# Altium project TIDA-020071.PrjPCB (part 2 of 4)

## Sheet 818-03.SchDoc
size A3; Date: Not shown in title block; ApprovedBy: Not shown in title block; CheckedBy: Not shown in title block; Author: Not shown in title block; CompanyName: Not shown in title block; Engineer: Not shown in title block; Organization: Not shown in title block; Address1: Not shown in title block; Address2: Not shown in title block; Address3: Not shown in title block; Address4: Not shown in title block; DocumentNumber: 4; Revision: Use project parameter SCH_Rev; SheetNumber: 4; SheetTotal: 15; PageSetup: Record=PageOptions¦CenterHorizontal=True¦CenterVertical=True¦PrintScale=1.00¦XCorrection=1.00¦YCorrection=1.00¦PrintKind=0¦BorderSize=5000000¦LeftOffset=0¦BottomOffset=0¦Orientation=2¦PaperLength=1000¦PaperWidth=1000¦Scale=100¦PaperSource=15¦PrintQuality=600¦MediaType=1¦DitherType=10¦PaperKind=Letter¦PrintScaleMode=1
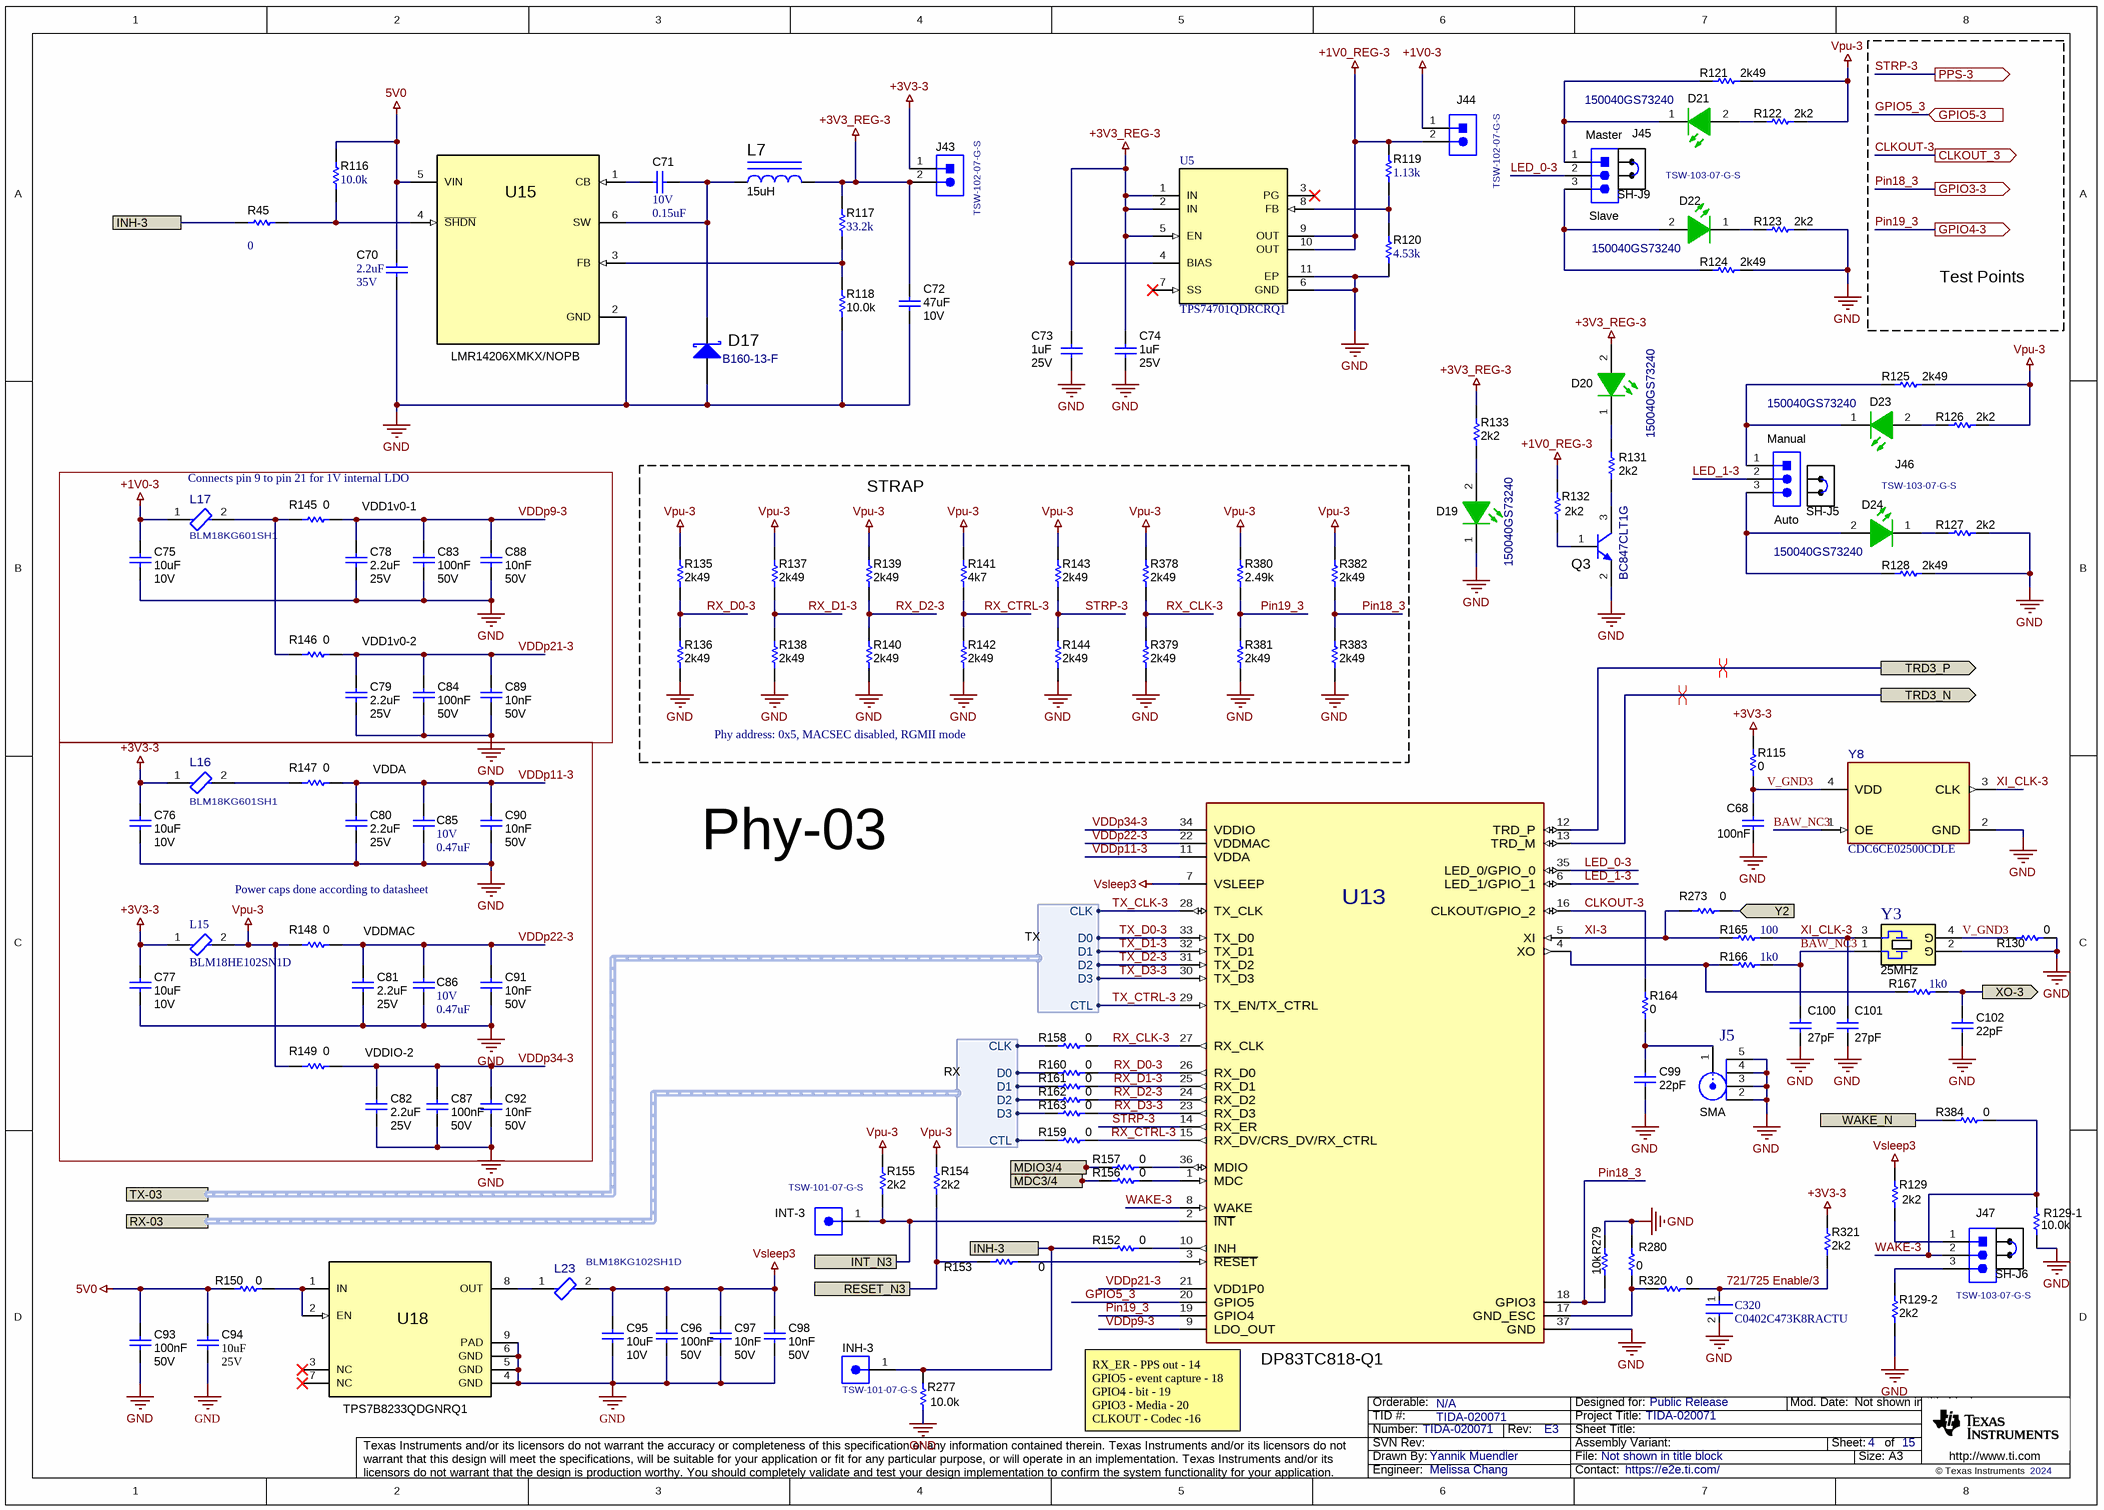
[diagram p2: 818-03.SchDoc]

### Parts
C68  ValueDisplayed: 100nF  [0402]  (hidden comment: C1005X5R1H104K050BB)
C70  VDC_V: 35V  ValueDisplayed: 2.2uF  [0603]  (hidden comment: C1608X5R1V225K080AC)
C71  VDC_V: 10V  ValueDisplayed: 0.15uF  [0402]  (hidden comment: GRM155R61A154KE19D)
C72  VDC_V: 10V  ValueDisplayed: 47uF  [0805_HV]  (hidden comment: C2012X5R1A476M125AC)
C73  VDC_V: 25V  ValueDisplayed: 1uF  [0402]  (hidden comment: GRM155R61E105KA12D)
C74  VDC_V: 25V  ValueDisplayed: 1uF  [0402]  (hidden comment: GRM155R61E105KA12D)
C75  VDC_V: 10V  ValueDisplayed: 10uF  [0402]  (hidden comment: GRM155R61A106ME11)
C76  VDC_V: 10V  ValueDisplayed: 10uF  [0402]  (hidden comment: GRM155R61A106ME11)
C77  VDC_V: 10V  ValueDisplayed: 10uF  [0402]  (hidden comment: GRM155R61A106ME11)
C78  VDC_V: 25V  ValueDisplayed: 2.2uF  [0402]  (hidden comment: C1005X5R1E225K050BC)
C79  VDC_V: 25V  ValueDisplayed: 2.2uF  [0402]  (hidden comment: C1005X5R1E225K050BC)
C80  VDC_V: 25V  ValueDisplayed: 2.2uF  [0402]  (hidden comment: C1005X5R1E225K050BC)
C81  VDC_V: 25V  ValueDisplayed: 2.2uF  [0402]  (hidden comment: C1005X5R1E225K050BC)
C82  VDC_V: 25V  ValueDisplayed: 2.2uF  [0402]  (hidden comment: C1005X5R1E225K050BC)
C83  VDC_V: 50V  ValueDisplayed: 100nF  [0402]  (hidden comment: C1005X5R1H104K050BB)
C84  VDC_V: 50V  ValueDisplayed: 100nF  [0402]  (hidden comment: C1005X5R1H104K050BB)
C85  VDC_V: 10V  ValueDisplayed: 0.47uF  [0402]  (hidden comment: GRM155R61A474KE15D)
C86  VDC_V: 10V  ValueDisplayed: 0.47uF  [0402]  (hidden comment: GRM155R61A474KE15D)
C87  VDC_V: 50V  ValueDisplayed: 100nF  [0402]  (hidden comment: C1005X5R1H104K050BB)
C88  VDC_V: 50V  ValueDisplayed: 10nF  [0402]  (hidden comment: C0402C103J5RACTU)
C89  VDC_V: 50V  ValueDisplayed: 10nF  [0402]  (hidden comment: C0402C103J5RACTU)
C90  VDC_V: 50V  ValueDisplayed: 10nF  [0402]  (hidden comment: C0402C103J5RACTU)
C91  VDC_V: 50V  ValueDisplayed: 10nF  [0402]  (hidden comment: C0402C103J5RACTU)
C92  VDC_V: 50V  ValueDisplayed: 10nF  [0402]  (hidden comment: C0402C103J5RACTU)
C93  VDC_V: 50V  ValueDisplayed: 100nF  [0402]  (hidden comment: C1005X5R1H104K050BB)
C94  VDC_V: 25V  ValueDisplayed: 10uF  [0603]  (hidden comment: C1608X5R1E106M080AC)
C95  VDC_V: 10V  ValueDisplayed: 10uF  [0402]  (hidden comment: GRM155R61A106ME11)
C96  VDC_V: 50V  ValueDisplayed: 100nF  [0402]  (hidden comment: C1005X5R1H104K050BB)
C97  VDC_V: 50V  ValueDisplayed: 10nF  [0402]  (hidden comment: C0402C103J5RACTU)
C98  VDC_V: 50V  ValueDisplayed: 10nF  [0402]  (hidden comment: C0402C103J5RACTU)
C99  ValueDisplayed: 22pF  [0402]  (hidden comment: GRM1555C1H220FA01D)
C100  ValueDisplayed: 27pF  [0402]  (hidden comment: C0402C270J5GACTU)
C101  ValueDisplayed: 27pF  [0402]  (hidden comment: C0402C270J5GACTU)
C102  ValueDisplayed: 22pF  [0402]  (hidden comment: GRM1555C1H220FA01D)
C320  C0402C473K8RACTU  [FP-C0402-BB-MFG]
D17  B160-13-F  [SMA]
D19  150040GS73240  [WL-SMCC_0402_Green]
D20  150040GS73240  [WL-SMCC_0402_Green]
D21  150040GS73240  [WL-SMCC_0402_Green]
D22  150040GS73240  [WL-SMCC_0402_Green]
D23  150040GS73240  [WL-SMCC_0402_Green]
D24  150040GS73240  [WL-SMCC_0402_Green]
INH-3  TSW-101-07-G-S  [TSW-101-07-G-S]
INT-3  TSW-101-07-G-S  [TSW-101-07-G-S]
J5  CompType: SMA  [AMPHENOL_901-144-8RFX]  (hidden comment: 901-144-8RFX)
J43  TSW-102-07-G-S  [TSW-102-07-G-S]
J44  TSW-102-07-G-S  [TSW-102-07-G-S]
J45  TSW-103-07-G-S  [TSW-103-07-G-S]
J46  TSW-103-07-G-S  [TSW-103-07-G-S]
J47  TSW-103-07-G-S  [TSW-103-07-G-S]
L7  ValueDisplayed: 15uH  [WE-TPC-LH]  (hidden comment: 744053150)
L15  BLM18HE102SN1D  [FP-BLM18-0_15-t0_8-MFG]
L16  BLM18KG601SH1  [FP-BLM18KG601SH1_0603 (1608 Metric)-MFG]
L17  BLM18KG601SH1  [FP-BLM18KG601SH1_0603 (1608 Metric)-MFG]
L23  BLM18KG102SH1D  [FP-BLM18KG102SH1D_0603-MFG]
Q3  BC847CLT1G  [SOT-23]
R45  ValueDisplayed: 0  [0402]  (hidden comment: CRCW04020000Z0ED)
R115  ValueDisplayed: 0  [0402]  (hidden comment: ERJ-2GE0R00X)
R116  ValueDisplayed: 10.0k  [0402]  (hidden comment: CRCW040210K0FKED)
R117  ValueDisplayed: 33.2k  [0402]  (hidden comment: CRCW040233K2FKED)
R118  ValueDisplayed: 10.0k  [0402]  (hidden comment: CRCW040210K0FKED)
R119  ValueDisplayed: 1.13k  [0402]  (hidden comment: CRCW04021K13FKED)
R120  ValueDisplayed: 4.53k  [0402]  (hidden comment: CRCW04024K53FKED)
R121  ValueDisplayed: 2k49  [0402]  (hidden comment: CRCW04022K49FKED)
R122  ValueDisplayed: 2k2  [0402]  (hidden comment: CRCW04022K20JNED)
R123  ValueDisplayed: 2k2  [0402]  (hidden comment: CRCW04022K20JNED)
R124  ValueDisplayed: 2k49  [0402]  (hidden comment: CRCW04022K49FKED)
R125  ValueDisplayed: 2k49  [0402]  (hidden comment: CRCW04022K49FKED)
R126  ValueDisplayed: 2k2  [0402]  (hidden comment: CRCW04022K20JNED)
R127  ValueDisplayed: 2k2  [0402]  (hidden comment: CRCW04022K20JNED)
R128  ValueDisplayed: 2k49  [0402]  (hidden comment: CRCW04022K49FKED)
R129  ValueDisplayed: 2k2  [0402]  (hidden comment: CRCW04022K20JNED)
R129-1  ValueDisplayed: 10.0k  [0402]  (hidden comment: CRCW040210K0FKED)
R129-2  ValueDisplayed: 2k2  [0402]  (hidden comment: CRCW04022K20JNED)
R130  ValueDisplayed: 0  [0402]  (hidden comment: ERJ-2GE0R00X)
R131  ValueDisplayed: 2k2  [0402]  (hidden comment: CRCW04022K20JNED)
R132  ValueDisplayed: 2k2  [0402]  (hidden comment: CRCW04022K20JNED)
R133  ValueDisplayed: 2k2  [0402]  (hidden comment: CRCW04022K20JNED)
R135  ValueDisplayed: 2k49  [0402]  (hidden comment: CRCW04022K49FKED)
R136  ValueDisplayed: 2k49  [0402]  (hidden comment: CRCW04022K49FKED)
R137  ValueDisplayed: 2k49  [0402]  (hidden comment: CRCW04022K49FKED)
R138  ValueDisplayed: 2k49  [0402]  (hidden comment: CRCW04022K49FKED)
R139  ValueDisplayed: 2k49  [0402]  (hidden comment: CRCW04022K49FKED)
R140  ValueDisplayed: 2k49  [0402]  (hidden comment: CRCW04022K49FKED)
R141  ValueDisplayed: 4k7  [0402]  (hidden comment: RC0402FR-074K7L)
R142  ValueDisplayed: 2k49  [0402]  (hidden comment: CRCW04022K49FKED)
R143  ValueDisplayed: 2k49  [0402]  (hidden comment: CRCW04022K49FKED)
R144  ValueDisplayed: 2k49  [0402]  (hidden comment: CRCW04022K49FKED)
R145  ValueDisplayed: 0  [0402]  (hidden comment: CRCW04020000Z0EDHP)
R146  ValueDisplayed: 0  [0402]  (hidden comment: CRCW04020000Z0EDHP)
R147  ValueDisplayed: 0  [0402]  (hidden comment: CRCW04020000Z0EDHP)
R148  ValueDisplayed: 0  [0402]  (hidden comment: CRCW04020000Z0EDHP)
R149  ValueDisplayed: 0  [0402]  (hidden comment: CRCW04020000Z0EDHP)
R150  ValueDisplayed: 0  [0402]  (hidden comment: CRCW04020000Z0EDHP)
R152  ValueDisplayed: 0  [0402]  (hidden comment: CRCW04020000Z0EDHP)
R153  ValueDisplayed: 0  [0402]  (hidden comment: CRCW04020000Z0EDHP)
R154  ValueDisplayed: 2k2  [0402]  (hidden comment: CRCW04022K20JNED)
R155  ValueDisplayed: 2k2  [0402]  (hidden comment: CRCW04022K20JNED)
R156  ValueDisplayed: 0  [0402]  (hidden comment: CRCW04020000Z0EDHP)
R157  ValueDisplayed: 0  [0402]  (hidden comment: CRCW04020000Z0EDHP)
R158  ValueDisplayed: 0  [0402]  (hidden comment: CRCW04020000Z0EDHP)
R159  ValueDisplayed: 0  [0402]  (hidden comment: CRCW04020000Z0EDHP)
R160  ValueDisplayed: 0  [0402]  (hidden comment: CRCW04020000Z0EDHP)
R161  ValueDisplayed: 0  [0402]  (hidden comment: CRCW04020000Z0EDHP)
R162  ValueDisplayed: 0  [0402]  (hidden comment: CRCW04020000Z0EDHP)
R163  ValueDisplayed: 0  [0402]  (hidden comment: CRCW04020000Z0EDHP)
R164  ValueDisplayed: 0  [0402]  (hidden comment: ERJ-2GE0R00X)
R165  ValueDisplayed: 100  [0402]  (hidden comment: CRCW0402100RFKED)
R166  ValueDisplayed: 1k0  [0402]  (hidden comment: CRCW04021K00FKED)
R167  ValueDisplayed: 1k0  [0402]  (hidden comment: CRCW04021K00FKED)
R273  ValueDisplayed: 0  [0402]  (hidden comment: ERJ-2GE0R00X)
R277  ValueDisplayed: 10.0k  [0402]  (hidden comment: CRCW040210K0FKED)
R279  ValueDisplayed: 10k  [0402]  (hidden comment: ERJ-2RKF1002X)
R280  ValueDisplayed: 0  [0402]  (hidden comment: ERJ-2GE0R00X)
R320  ValueDisplayed: 0  [0402]  (hidden comment: CRCW04020000Z0EDHP)
R321  ValueDisplayed: 2k2  [0402]  (hidden comment: CRCW04022K20JNED)
R378  ValueDisplayed: 2k49  [0402]  (hidden comment: CRCW04022K49FKED)
R379  ValueDisplayed: 2k49  [0402]  (hidden comment: CRCW04022K49FKED)
R380  ValueDisplayed: 2.49k  [0402]  (hidden comment: CRCW04022K49FKED)
R381  ValueDisplayed: 2k49  [0402]  (hidden comment: CRCW04022K49FKED)
R382  ValueDisplayed: 2k49  [0402]  (hidden comment: CRCW04022K49FKED)
R383  ValueDisplayed: 2k49  [0402]  (hidden comment: CRCW04022K49FKED)
R384  ValueDisplayed: 0  [0402]  (hidden comment: CRCW04020000Z0EDHP)
SH-J5  881545-2  [TE_881545-2]  (value not drawn)  (mechanical)
SH-J6  881545-2  [TE_881545-2]  (value not drawn)  (mechanical)
SH-J9  881545-2  [TE_881545-2]  (value not drawn)  (mechanical)
U5  TPS74701QDRCRQ1  [DRC0010A]
U13  PartNumber: DP83TC818-Q1  [RHA0036A-MFG]  (hidden comment: DP83TC812R-Q1)
U15  LMR14206XMKX/NOPB  [DDC0006A_N]
U18  TPS7B8233QDGNRQ1  [DGN0008D_N]
Y3  Frequency_Fixed: 25MHz  [Abracon_ABM8AIG]  (hidden comment: ABM8AIG-25.000MHZ-12-2Z-T3)
Y8  CDC6CE02500CDLE  [DLE0004A-MFG]

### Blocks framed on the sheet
STRAP: R135-R144 R378-R383

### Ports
CLKOUT_3 (out), GPIO3-3 (out), GPIO4-3 (out), GPIO5-3 (in), INH-3, INT_N3, MDC3/4, MDIO3/4, PPS-3 (out), RESET_N3, RX-03 (harness RX), TRD3_N (out), TRD3_P (out), TX-03 (harness TX), WAKE_N, XO-3 (out), Y2 (in)

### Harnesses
TX: D0, D1, D2, D3, CTL, CLK
RX: D0, D1, D2, D3, CTL, CLK

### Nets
5V0: C70.1 C93.1 C94.1 R116.2 R150.2 U15.5(VIN)
+1V0-3: C75.1 J44.1 L17.1
+1V0_REG-3: J44.2 R119.2 R132.2 U5.9(OUT) U5.10(OUT)
+3V3-3: C76.1 C77.1 J43.1 L15.1 L16.1 R115.1 R321.1
+3V3_REG-3: C72.1 C73.1 C74.1 D20.2(A) J43.2 L7.2 R117.2 R133.2 U5.1(IN) U5.2(IN) U5.4(BIAS) U5.5(EN)
GND: C68.2 C70.2 C72.2 C73.2 C74.2 C75.2 C76.2 C77.2 C78.2 C79.2 C80.2 C81.2 C82.2 C83.2 C84.2 C85.2 C86.2 C87.2 C88.2 C89.2 C90.2 C91.2 C92.2 C93.2 C94.2 C95.2 C96.2 C97.2 C98.2 C99.2 C100.2 C101.2 C102.2 C320.2 D17.2(A) D19.1(K) J5.2 J5.3 J5.4 J5.5 Q3.2(E) R118.1 R120.1 R123.2 R124.2 R127.2 R128.2 R129-1.1 R129-2.2 R130.2 R136.1 R138.1 R140.1 R142.1 R144.1 R277.1 R279.1 R280.1 R379.1 R381.1 R383.1 U5.6(GND) U5.11(EP) U13.37(GND) U15.2(GND) U18.4(GND) U18.5(GND) U18.6(GND) U18.9(PAD) Y3.2(GND) Y8.2(GND)
Vpu-3: L15.2 R121.2 R122.2 R125.2 R126.2 R135.2 R137.2 R139.2 R141.2 R143.2 R148.2 R149.2 R154.2 R155.2 R378.2 R380.2 R382.2
Vsleep3: C95.1 C96.1 C97.1 C98.1 L23.2 R129.1 U13.7(VSLEEP)
721/725 Enable/3: C320.1 R320.1 R321.2
BAW_NC3: C100.1 R166.1 Y3.1 Y8.1(OE)
CLKOUT-3: R164.1 R166.2 R167.2 U13.4(XO) U13.16(CLKOUT/GPIO_2) ; port CLKOUT_3
GPIO5_3: U13.20(GPIO5) ; port GPIO5-3
INH-3: INH-3.1 R45.1 R152.2 R277.2 ; port INH-3
INT_N3: INT-3.1 R155.1 U13.2(~{INT}) ; port INT_N3
LED_0-3: J45.2 U13.35(LED_0/GPIO_0)
LED_1-3: J46.2 U13.6(LED_1/GPIO_1)
MDC3/4: R156.2 ; port MDC3/4
MDIO3/4: R157.2 ; port MDIO3/4
P0-R1-RCLK: R158.2 ; port RX-03.CLK
P0-R1-RCTL: R159.2 ; port RX-03.CTL
P0-R1-RD0: R160.2 ; port RX-03.D0
P0-R1-RD1: R161.2 ; port RX-03.D1
P0-R1-RD2: R162.2 ; port RX-03.D2
P0-R1-RD3: R163.2 ; port RX-03.D3
Pin18_3: R279.2 R382.1 R383.2 U13.18(GPIO3) ; port GPIO3-3
Pin19_3: R380.1 R381.2 U13.19(GPIO4) ; port GPIO4-3
RESET_N3: R153.2 R154.1 ; port RESET_N3
RX_CLK-3: R158.1 R378.1 R379.2 U13.27(RX_CLK)
RX_CTRL-3: R141.1 R142.2 R159.1 U13.15(RX_DV/CRS_DV/RX_CTRL)
RX_D0-3: R135.1 R136.2 R160.1 U13.26(RX_D0)
RX_D1-3: R137.1 R138.2 R161.1 U13.25(RX_D1)
RX_D2-3: R139.1 R140.2 R162.1 U13.24(RX_D2)
RX_D3-3: R163.1 U13.23(RX_D3)
STRP-3: R143.1 R144.2 U13.14(RX_ER) ; port PPS-3
TRD3_N: U13.13(TRD_M) ; port TRD3_N
TRD3_P: U13.12(TRD_P) ; port TRD3_P
TX_CLK-3: U13.28(TX_CLK) ; port TX-03.CLK
TX_CTRL-3: U13.29(TX_EN/TX_CTRL) ; port TX-03.CTL
TX_D0-3: U13.33(TX_D0) ; port TX-03.D0
TX_D1-3: U13.32(TX_D1) ; port TX-03.D1
TX_D2-3: U13.31(TX_D2) ; port TX-03.D2
TX_D3-3: U13.30(TX_D3) ; port TX-03.D3
V_GND3: C68.1 R115.2 R130.1 Y3.4(GND) Y8.4(VDD)
VDDp9-3: C78.1 C83.1 C88.1 R145.1 U13.9(LDO_OUT)
VDDp11-3: C80.1 C85.1 C90.1 R147.1 U13.11(VDDA)
VDDp21-3: C79.1 C84.1 C89.1 R146.1 U13.21(VDD1P0)
VDDp22-3: C81.1 C86.1 C91.1 R148.1 U13.22(VDDMAC)
VDDp34-3: C82.1 C87.1 C92.1 R149.1 U13.34(VDDIO)
WAKE-3: J47.2 R129-1.2 R384.1 U13.8(WAKE)
WAKE_N: R384.2 ; port WAKE_N
XI-3: R165.2 R273.1 U13.5(XI)
XI_CLK-3: C101.1 R165.1 Y3.3 Y8.3(CLK)
XO-3: C102.1 R167.1 ; port XO-3
Y2: R273.2 ; port Y2
NetC71_1: C71.1 D17.1(K) L7.1 U15.6(SW)
NetC71_2: C71.2 U15.1(CB)
NetC99_1: C99.1 J5.1 R164.2
NetD19_2: D19.2(A) R133.1
NetD20_1: D20.1(K) R131.2
NetD21_1: D21.1(K) J45.1 R121.1
NetD21_2: D21.2(A) R122.1
NetD22_1: D22.1(K) R123.1
NetD22_2: D22.2(A) J45.3 R124.1
NetD23_1: D23.1(K) J46.1 R125.1
NetD23_2: D23.2(A) R126.1
NetD24_1: D24.1(K) R127.1
NetD24_2: D24.2(A) J46.3 R128.1
NetJ47_1: J47.1 R129.2
NetJ47_3: J47.3 R129-2.1
NetL16_2: L16.2 R147.2
NetL17_2: L17.2 R145.2 R146.2
NetL23_1: L23.1 U18.8(OUT)
NetQ3_1: Q3.1(B) R132.1
NetQ3_3: Q3.3(C) R131.1
NetR45_2: R45.2 R116.1 U15.4(~{SHDN})
NetR117_1: R117.1 R118.2 U15.3(FB)
NetR119_1: R119.1 R120.2 U5.8(FB)
NetR150_1: R150.1 U18.1(IN) U18.2(EN)
NetR152_1: R152.1 U13.10(INH)
NetR153_1: R153.1 U13.3(~{RESET})
NetR156_1: R156.1 U13.1(MDC)
NetR157_1: R157.1 U13.36(MDIO)
NetR280_2: R280.2 R320.2 U13.17(GND_ESC)

Not connected (* = marked no-connect by the designer): U5 3(PG)* 7(SS)*; U18 3(NC)* 7(NC)*

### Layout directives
differential pair: TRD3_N, TRD3_P

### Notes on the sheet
- (near J45) Master
- (near J45) Slave
- Test Points
- (near J46) Manual
- Connects pin 9 to pin 21 for 1V internal LDO
- VDD1v0-1
- Auto
- VDD1v0-2
- VDDA
- Phy address: 0x5, MACSEC disabled, RGMII mode
- Phy-03
- Power caps done according to datasheet
- VDDMAC
- VDDIO-2
- (near U13) RX_ER - PPS out - 14
  GPIO5 - event capture - 18
  GPIO4 - bit - 19                                     GPIO3 - Media - 20
  CLKOUT - Codec -16

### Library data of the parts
C68 = CMP-0006279-2: CAP, CERM, 0.1 uF, 50 V, +/- 10%, X5R, 0402; Manufacturer: TDK; TaMin_C: -55°C; ESR_ohm: 0.039064; Polarized: N; SizeAreaWB_mm2: 3; Value1: 0.039064 ohm; U/M: EA; Value: 0.1uF; TaMax_C: 85°C; SizeZ_mm: 0.6; SizeX_mm: 1; SizeY_mm: 0.5; Value2: 50V; IRMS_A: 814.669mA; AEC Category: Q200
C70 = CMP-0007020-5: CAP, CERM, 2.2 uF, 35 V, +/- 10%, X5R, 0603; Manufacturer: TDK; TaMin_C: -55°C; ESR_ohm: 7.674m; Polarized: N; SizeAreaWB_mm2: 4.68; Value1: 0.007674 ohm; U/M: EA; Value: 2.2uF; TaMax_C: 85°C; SizeZ_mm: 1; SizeX_mm: 1.6; SizeY_mm: 0.8; SizeArea_mm2: 1.28; Cap_F: 2.2µF; IRMS_A: 1.87823A; AEC Category: Q200
C71 = CMP-0006567-2: CAP, CERM, 0.15 uF, 10 V, +/- 10%, X5R, 0402; Manufacturer: MuRata; TaMin_C: -55°C; Polarized: N; SizeAreaWB_mm2: 3; Value1: Unknown; U/M: EA; Value: 0.15uF; TaMax_C: 85°C; SizeZ_mm: 0.6; SizeX_mm: 1; SizeY_mm: 0.5; Cap_F: 150nF; AEC Category: Q200
C72 = CMP-0007825-2: CAP, CERM, 47 uF, 10 V, +/- 20%, X5R, 0805; Manufacturer: TDK; TaMin_C: -55°C; ESR_ohm: 2.94m; Polarized: N; SizeAreaWB_mm2: 6.75; Value1: 0.00294 ohm; U/M: EA; Value: 47uF; TaMax_C: 85°C; SizeZ_mm: 1.45; SizeX_mm: 2; SizeY_mm: 1.25; Cap_Case: 0805; SizeArea_mm2: 2.5; Cap_F: 47µF; IRMS_A: 3.80451A; AEC Category: Q200
C73 C74 = CMP-0006608-2: CAP, CERM, 1 uF, 25 V, +/- 10%, X5R, 0402; Manufacturer: MuRata; TaMin_C: -55°C; Polarized: N; SizeAreaWB_mm2: 3; Value1: Unknown; U/M: EA; Value: 1uF; TaMax_C: 85°C; SizeZ_mm: 0.6; SizeX_mm: 1; SizeY_mm: 0.5; Cap_F: 1µF; AEC Category: Q200
C75-C77 C95 = CMP-0006564-2: CAP, CERM, 10 uF, 10 V, +/- 20%, X5R, 0402; Manufacturer: MuRata; TaMin_C: -55°C; Polarized: N; SizeAreaWB_mm2: 3; Value1: Unknown; U/M: EA; Value: 10uF; TaMax_C: 85°C; SizeZ_mm: 0.6; SizeX_mm: 1; SizeY_mm: 0.5; Cap_F: 10µF; AEC Category: Q200
C78-C82 = CMP-0006278-2: CAP, CERM, 2.2 uF, 25 V, +/- 10%, X5R, 0402; Manufacturer: TDK; TaMin_C: -55°C; Polarized: N; SizeAreaWB_mm2: 3; Value1: Unknown; U/M: EA; Value: 2.2uF; TaMax_C: 85°C; SizeZ_mm: 0.6; SizeX_mm: 1; SizeY_mm: 0.5; Cap_F: 2.2µF; AEC Category: Q200
C83 C84 C87 C93 C96 = CMP-0006279-2: CAP, CERM, 0.1 uF, 50 V, +/- 10%, X5R, 0402; Manufacturer: TDK; TaMin_C: -55°C; ESR_ohm: 39.064m; Polarized: N; SizeAreaWB_mm2: 3; Value1: 0.039064 ohm; U/M: EA; Value: 0.1uF; TaMax_C: 85°C; SizeZ_mm: 0.6; SizeX_mm: 1; SizeY_mm: 0.5; IRMS_A: 814.669mA; AEC Category: Q200
C85 C86 = CMP-0006580-2: CAP, CERM, 0.47 uF, 10 V, +/- 10%, X5R, 0402; Manufacturer: MuRata; TaMin_C: -55°C; Polarized: N; SizeAreaWB_mm2: 3; Value1: Unknown; U/M: EA; Value: 0.47uF; TaMax_C: 85°C; SizeZ_mm: 0.6; SizeX_mm: 1; SizeY_mm: 0.5; Cap_F: 470nF; AEC Category: Q200
C88-C92 C97 C98 = CMP-0006236-2: CAP, CERM, 0.01 uF, 50 V, +/- 5%, X7R, 0402; Manufacturer: Kemet; TaMin_C: -55°C; Polarized: N; SizeAreaWB_mm2: 3; Value1: Unknown; U/M: EA; Value: 0.01uF; TaMax_C: 125°C; SizeZ_mm: 0.6; SizeX_mm: 1; SizeY_mm: 0.5; AEC Category: Q200
C94 = CMP-0007007-5: CAP, CERM, 10 uF, 25 V, +/- 20%, X5R, 0603; Manufacturer: TDK; TaMin_C: -55°C; ESR_ohm: 4.639m; Polarized: N; SizeAreaWB_mm2: 4.68; Value1: 0.004639 ohm; U/M: EA; Value: 10uF; TaMax_C: 85°C; SizeZ_mm: 1; SizeX_mm: 1.6; SizeY_mm: 0.8; SizeArea_mm2: 1.28; Cap_F: 10µF; IRMS_A: 2.41407A; AEC Category: Q200
C99 C102 = CMP-0006438-2: CAP, CERM, 22 pF, 50 V, +/- 1%, C0G/NP0, 0402; Manufacturer: MuRata; TaMin_C: -55°C; Polarized: N; SizeAreaWB_mm2: 3; Value1: Unknown; U/M: EA; Value: 22pF; TaMax_C: 125°C; SizeZ_mm: 0.6; SizeX_mm: 1; SizeY_mm: 0.5; Value2: 50V; AEC Category: Q200
C100 C101 = CMP-0750098-1: CAP, CERM, 27 pF, 50 V,+/- 5%, C0G/NP0, 0402; Manufacturer: Kemet; SizeX_mm: 1; TaMin_C: -55°C; Value: 27pF; Polarized: N; SizeAreaWB_mm2: 3; SizeArea_mm2: 0.5; Green_REACh: Passed; Green_Lifecycle: Active; Value2: 50V; U/M: EA; AEC Category: Q200; SizeZ_mm: 0.6; TaMax_C: 125°C
C320 = CMP-2008-02147-2: Cap Ceramic 0.047uF 10V X7R 10% SMD 0402 125°C Paper T/R; Manufacturer: Kemet; Temperature Coefficient: 15%; Value: 47,000 pF; Tolerance: 0.1
D17 = CMP-0028389-2: Diode, Schottky, 60 V, 1 A, SMA; Manufacturer: Diodes Inc.; Green_Lifecycle: Not Set; SizeAreaWB_mm2: 37.3428; Green_REACh: Incomplete; TJmax_C: 150°C; AEC Category: Q101; SizeZ_mm: 2.87; RJC_CperW: 20; Io_A: 1A; SizeArea_mm2: 16.3228; Vf_V: 700mV; Value2: 0.7V; SizeY_mm: 2.92; Vr_V: 60V; SizeX_mm: 5.59; Value: 60V
D19-D24 = CMP-0081765-2: LED, Green, SMD; Manufacturer: Wurth Elektronik; Vr_V: 5V; Io_A: 20mA; Tjmax_C: 95°C; Ir_A: 10µA; Power_TotalModule: 99mW; Value2: 3.2V; SizeArea_mm2: 0.5; SizeX_mm: 1; Value1: 0.099W; Angle: 120; Type: InGaN; SizeAreaWB_mm2: 3
INH-3 INT-3 = CMP-0075403-1: Header, 100mil, 1pos, Gold, TH; Manufacturer: Samtec; Pitch_mm: 2.54; Cert_VDE: N; Gender: Male; Cert_CSA: Y; Voltage_V: 550V; Green_REACh: Passed; Current_A: 6.3A; CT: False; Green_Lifecycle: Active; Row_Count: 1; CNHeader: True
J5 = CMP-0055833-1: SMA Straight Jack, Gold, 50 Ohm, TH; Manufacturer: Amphenol RF; CNHeader: FALSE; Green_Lifecycle: Not Set; Green_REACh: Incomplete; CT: TRUE
J43 J44 = CMP-0075405-3: Header, 100mil, 2x1, Gold, TH; Manufacturer: Samtec; Pitch_mm: 2.54; Cert_VDE: N; Gender: Male; Cert_CSA: Y; Voltage_V: 550V; Green_REACh: Passed; Current_A: 6.3A; Green_Lifecycle: Active; Row_Count: 1
J45-J47 = CMP-0075407-2: Header, 100mil, 3x1, Gold, TH; Manufacturer: Samtec; Pitch_mm: 2.54; Cert_VDE: N; Gender: Male; Cert_CSA: Y; Voltage_V: 550V; Green_REACh: Passed; Current_A: 6.3A; Green_Lifecycle: Active; Row_Count: 1
L7 = CMP-0064420-2: Inductor, Shielded Drum Core, Ferrite, 15 uH, 1.15 A, 0.07 ohm, SMD; Manufacturer: Wurth Elektronik; Isat: 1.15A @ 35% inductance drop; Irms: 1.38A @ 30C rise; Green_Lifecycle: Active; SizeAreaWB_mm2: 60.84; DCR_ohm: 0.07; Green_REACh: Passed; Value: 15uH; Imax_A: 1.15A; SizeZ_mm: 2.8; SizeX_mm: 5.8; SizeArea_mm2: 33.64; Ind_H: 15µH; AEC Category: Q200
L15 = CMP-0686-00363-3: Chip Ferrite Bead, 0603, 1000Ω @ 100MHz, 0.35Ω, 25%, 600mA; DC Resistance (DCR): 350mR; Impedance: 1kR; Number of Circuits: 1; Material: Steel
L16 L17 = CMP-0089848-1: 600 Ohms @ 100MHz 1 Power Line Ferrite Bead 0603 (1608 Metric) 1.3A 150mOhm; Manufacturer: Murata; Tolerance_%: 25%; SizeZ_mm: 0.95mm; Impedance At Frequency: 600Ω @ 100MHz; AEC Qualified: Yes; AEC Grade: Grade 1; DCR_ohm: 0.15
L23 = CMP-0089381-1: 1 kOhms @ 100MHz 1 Power Line Ferrite Bead 0603 (1608 Metric) 1A 200mOhm; Manufacturer: Murata; AEC Grade: Grade 1; AEC Qualified: Yes; DCR_ohm: 0.2; Impedance At Frequency: 1kΩ @ 100MHz; SizeZ_mm: 0.95mm; Tolerance_%: 25%
Q3 = CMP-0000376-2: Transistor, NPN, 45 V, 0.1 A, SOT-23; Manufacturer: ON Semiconductor; TaMax_C: 150°C; Value2: 800; Value1: 0.1 A; Vcesat1_V: 700mV; SizeX_mm: 2.5; SizeY_mm: 3; TaMin_C: -55°C; IcRated_A: 100mA; CompType: BJT; SizeZ_mm: 1.1; Value: 45 V; SizeArea_mm2: 7.5; NPN: 1; Vceo_V: 45V; PNP: 0; AEC Category: Q101; SizeAreaWB_mm2: 14; U/M: EA
R45 = CMP-0026822-1: RES, 0, 5%, 0.063 W, 0402; Manufacturer: Vishay-Dale; Power_W: 63mW; TempCo: 200 ppm/C; Value_Code: 0000; U/M: EA; Value: 0; EIA_Code: E24; SizeX_mm: 1; SizeY_mm: 0.5; SizeZ_mm: 0.6; Value2: 0.063W; VDC_V: 50V; AEC Category: Q200
R115 R130 R164 R273 R280 = CMP-0026992-3: RES, 0, 5%, 0.1 W, AEC-Q200 Grade 0, 0402; Manufacturer: Panasonic; Power_W: 100mW; TempCo: 600 ppm/C; Value_Code: 0000; Value: 0; EIA_Code: E24; SizeX_mm: 1; SizeY_mm: 0.5; SizeZ_mm: 0.6; Value2: 0.1W; AEC Qualified: Y; AEC Category: Q200; VDC_V: 50V; SizeAreaWB_mm2: 3
R116 R118 = CMP-0025958-3: RES, 10.0 k, 1%, 0.063 W, AEC-Q200 Grade 0, 0402; Manufacturer: Vishay-Dale; Power_W: 63mW; TempCo: 100 ppm/C; Value_Code: 10k0; Value: 10.0k; EIA_Code: E96; Res_ohm: 10k; SizeX_mm: 1; SizeY_mm: 0.5; SizeZ_mm: 0.6; Value2: 0.063W; AEC Qualified: Y; VDC_V: 50V; AEC Category: Q200; AEC Grade: 0
R117 = CMP-0026298-2: RES, 33.2 k, 1%, 0.063 W, AEC-Q200 Grade 0, 0402; Manufacturer: Vishay-Dale; Power_W: 63mW; TempCo: 100 ppm/C; Value_Code: 33k2; Value: 33.2k; EIA_Code: E96; SizeX_mm: 1; SizeY_mm: 0.5; SizeZ_mm: 0.6; Value2: 0.063W; AEC Qualified: Y; VDC_V: 50V; AEC Category: Q200; AEC Grade: 0
R119 = CMP-0026076-3: RES, 1.13 k, 1%, 0.063 W, AEC-Q200 Grade 0, 0402; Manufacturer: Vishay-Dale; Power_W: 63mW; TempCo: 100 ppm/C; Value_Code: 1k13; Value: 1.13k; EIA_Code: E96; SizeX_mm: 1; SizeY_mm: 0.5; SizeZ_mm: 0.6; Value2: 0.063W; AEC Qualified: Y; VDC_V: 50V; AEC Category: Q200; AEC Grade: 0
R120 = CMP-0026410-2: RES, 4.53 k, 1%, 0.063 W, AEC-Q200 Grade 0, 0402; Manufacturer: Vishay-Dale; Power_W: 63mW; TempCo: 100 ppm/C; Value_Code: 4k53; Value: 4.53k; EIA_Code: E96; SizeX_mm: 1; SizeY_mm: 0.5; SizeZ_mm: 0.6; Value2: 0.063W; AEC Qualified: Y; VDC_V: 50V; AEC Category: Q200; AEC Grade: 0
R121 R124 R125 R128 R135-R140 R142-R144 R378 R379 R381-R383 = CMP-0026237-2: RES, 2.49 k, 1%, 0.063 W, AEC-Q200 Grade 0, 0402; Manufacturer: Vishay-Dale; Power_W: 63mW; TempCo: 100 ppm/C; Value: 2.49k; EIA_Code: E96; SizeX_mm: 1; SizeY_mm: 0.5; SizeZ_mm: 0.6; Value2: 0.063W; AEC Qualified: Y; VDC_V: 50V; AEC Category: Q200; AEC Grade: 0
R122 R123 R126 R127 R129 R129-2 R131-R133 R154 R155 R321 = CMP-0026890-5: RES, 2.2 k, 5%, 0.063 W, AEC-Q200 Grade 0, 0402; Manufacturer: Vishay-Dale; Power_W: 63mW; TempCo: 200 ppm/C; Value_Code: 2k20; Value: 2.2k; EIA_Code: E24; SizeX_mm: 1; SizeY_mm: 0.5; SizeZ_mm: 0.6; Value2: 0.063W; AEC Qualified: Y; VDC_V: 50V; AEC Category: Q200; AEC Grade: 0
R129-1 R277 = CMP-0025958-1: RES, 10.0 k, 1%, 0.063 W, 0402; Manufacturer: Vishay-Dale; Power_W: 63mW; TempCo: 100 ppm/C; Value_Code: 10k0; U/M: EA; Value: 10.0k; EIA_Code: E96; Res_ohm: 10k; SizeX_mm: 1; SizeY_mm: 0.5; SizeZ_mm: 0.6; Value2: 0.063W; VDC_V: 50V; AEC Category: Q200
R141 = CMP-0026739-1: RES, 4.70 k, 1%, 0.0625 W, 0402; Manufacturer: Yageo America; Power_W: 62.5mW; TempCo: 100 ppm/C; Value_Code: 4k70; U/M: EA; Value: 4.70k; Res_ohm: 4.7k; SizeX_mm: 1; SizeY_mm: 0.5; SizeZ_mm: 0.6; AEC Qualified: N; VDC_V: 50V; AEC Category: Q200
R145-R150 R152 R153 R156-R163 R320 R384 = CMP-0081856-1: RES, 0, 0%, 0.2 W, AEC-Q200 Grade 0, 0402; Manufacturer: Vishay-Dale; SizeAreaWB_mm2: 3; SizeArea_mm2: 0.5; AEC Qualified: Y; AEC Category: Q200; Value: 0; SizeZ_mm: 0.6; Power_W: 200mW; VDC_V: 50V; Value2: 0.2W; SizeX_mm: 1
R165 = CMP-0025951-3: RES, 100, 1%, 0.063 W, AEC-Q200 Grade 0, 0402; Manufacturer: Vishay-Dale; Power_W: 63mW; TempCo: 100 ppm/C; Value_Code: 100R; Value: 100; EIA_Code: E96; SizeX_mm: 1; SizeY_mm: 0.5; SizeZ_mm: 0.6; Value2: 0.063W; AEC Qualified: Y; VDC_V: 50V; AEC Category: Q200; AEC Grade: 0
R166 R167 = CMP-0026071-3: RES, 1.00 k, 1%, 0.063 W, AEC-Q200 Grade 0, 0402; Manufacturer: Vishay-Dale; Power_W: 63mW; TempCo: 100 ppm/C; Value_Code: 1k00; Value: 1.00k; EIA_Code: E96; Res_ohm: 1k; SizeX_mm: 1; SizeY_mm: 0.5; SizeZ_mm: 0.6; Value2: 0.063W; AEC Qualified: Y; VDC_V: 50V; AEC Category: Q200; AEC Grade: 0
R279 = CMP-0026992-3: RES, 10.0 k, 1%, 0.1 W, 0402; Manufacturer: Panasonic; PartNumber: ERJ-2GE0R00X; Power_W: 100mW; TempCo: 600 ppm/C; Value_Code: 0000; Value1: 5%; Value: 0; EIA_Code: E24; SizeX_mm: 1; SizeY_mm: 0.5; SizeZ_mm: 0.6; Value2: 0.1W; AEC Qualified: Y; AEC Category: Q200; VDC_V: 50V; SizeAreaWB_mm2: 3
R380 = CMP-0026237-2: RES, 2.49 k, 1%, 0.063 W, AEC-Q200 Grade 0, 0402; Manufacturer: Vishay-Dale; Power_W: 63mW; TempCo: 100 ppm/C; Value_Code: 2k49; Value: 2.49k; EIA_Code: E96; SizeX_mm: 1; SizeY_mm: 0.5; SizeZ_mm: 0.6; Value2: 0.063W; AEC Qualified: Y; VDC_V: 50V; AEC Category: Q200; AEC Grade: 0
SH-J5 SH-J6 SH-J9 = 881545-2: Shunt, 100mil, Gold plated, Black; Manufacturer: TE Connectivity
U5 = CMP-0036364-1: Single Output Automotive LDO, 500 mA, Adjustable 0.8 to 3.6 V Output, 0.8 to 5.5 V Input, with Programmable Soft Start, 10-pin SON (DRC), -40 to 125 degC, Green (RoHS & no Sb/Br); Manufacturer: Texas Instruments; Accuracy(%): 2; Vout Adj(Min)(V): 0.8; Vdo(Typ)(mV): 50; Vout Adj(Max)(V): 3.6; SubFamily: Single Channel LDO; Vin(Max)(V): 5.5; Iq(Typ)(mA): 1; Iout(Max)(A): 0.5
U13 = CMP-0089064-1: TC-10 Compliant 100Base-T1 Automotive Ethernet PHY; Manufacturer: Texas Instruments; SizeZ_mm: 1mm; AEC Qualified: Yes
U15 = CMP-0076377-2: SIMPLE SWITCHER(R) 4.5V to 42V, 0.6A Step-Down DC/DC Switching Regulator in SOT-23 Package, DDC0006A (SOT-23-T-6); Alternate PartNumber: LMR14206XMKE/NOPB; Manufacturer: Texas Instruments; SizeZ_mm: 0.87; SizeX_mm: 1.65; SizeY_mm: 2.95; SizeArea_mm2: 4.8675; CompType: IC; U/M: EA; SizeAreaWB_mm2: 10.4675
U18 = CMP-0013312-4: 300mA High-Voltage Ultra-Low-Iq Low-Dropout (LDO) Regulator, DGN0008D (VSSOP-8); Manufacturer: Texas Instruments; SizeX_mm: 5.05; SizeY_mm: 3.1; CompType: IC; SizeZ_mm: 1.1; SizeArea_mm2: 15.655; SizeAreaWB_mm2: 35.955; AEC Category: Q200; AEC Qualified: Y
Y3 = CMP-0004682-5: Crystal, 25 MHz, 12pF, AEC-Q200 Grade 1, SMD; Manufacturer: Abracon Corporation; TaMin_C: -40°C; Frequency Stability: 50 ppm; SizeAreaWB_mm2: 14.7; TaMax_C: 125°C; SizeZ_mm: 0.8; SizeX_mm: 2.5; SizeY_mm: 3.2; SizeArea_mm2: 8; AEC Category: Q200; AEC Grade: 1; AEC Qualified: Y
Y8 = CMP-0001498-1: Low Jitter, Low Power, LVCMOS Output, BAW Oscillator; Manufacturer: Texas Instruments; SizeZ_mm: 1mm; AEC Qualified: Yes; AEC Grade: Grade 1; Frequency Stability: 20ppm; Frequency_Fixed: 25MHz; Max Supply Current: 5mA; Max Supply Voltage: 3.63V; Min Supply Voltage: 1.62V; Standoff Height: 0mm

## Sheet 818-04.SchDoc
size A3; Date: Not shown in title block; ApprovedBy: Not shown in title block; CheckedBy: Not shown in title block; Author: Not shown in title block; CompanyName: Not shown in title block; Engineer: Not shown in title block; Organization: Not shown in title block; Address1: Not shown in title block; Address2: Not shown in title block; Address3: Not shown in title block; Address4: Not shown in title block; DocumentNumber: 5; Revision: Use project parameter SCH_Rev; SheetNumber: 5; SheetTotal: 15; PageSetup: Record=PageOptions¦CenterHorizontal=True¦CenterVertical=True¦PrintScale=1.00¦XCorrection=1.00¦YCorrection=1.00¦PrintKind=0¦BorderSize=5000000¦LeftOffset=0¦BottomOffset=0¦Orientation=2¦PaperLength=1000¦PaperWidth=1000¦Scale=100¦PaperSource=15¦PrintQuality=600¦MediaType=1¦DitherType=10¦PaperKind=Letter¦PrintScaleMode=1
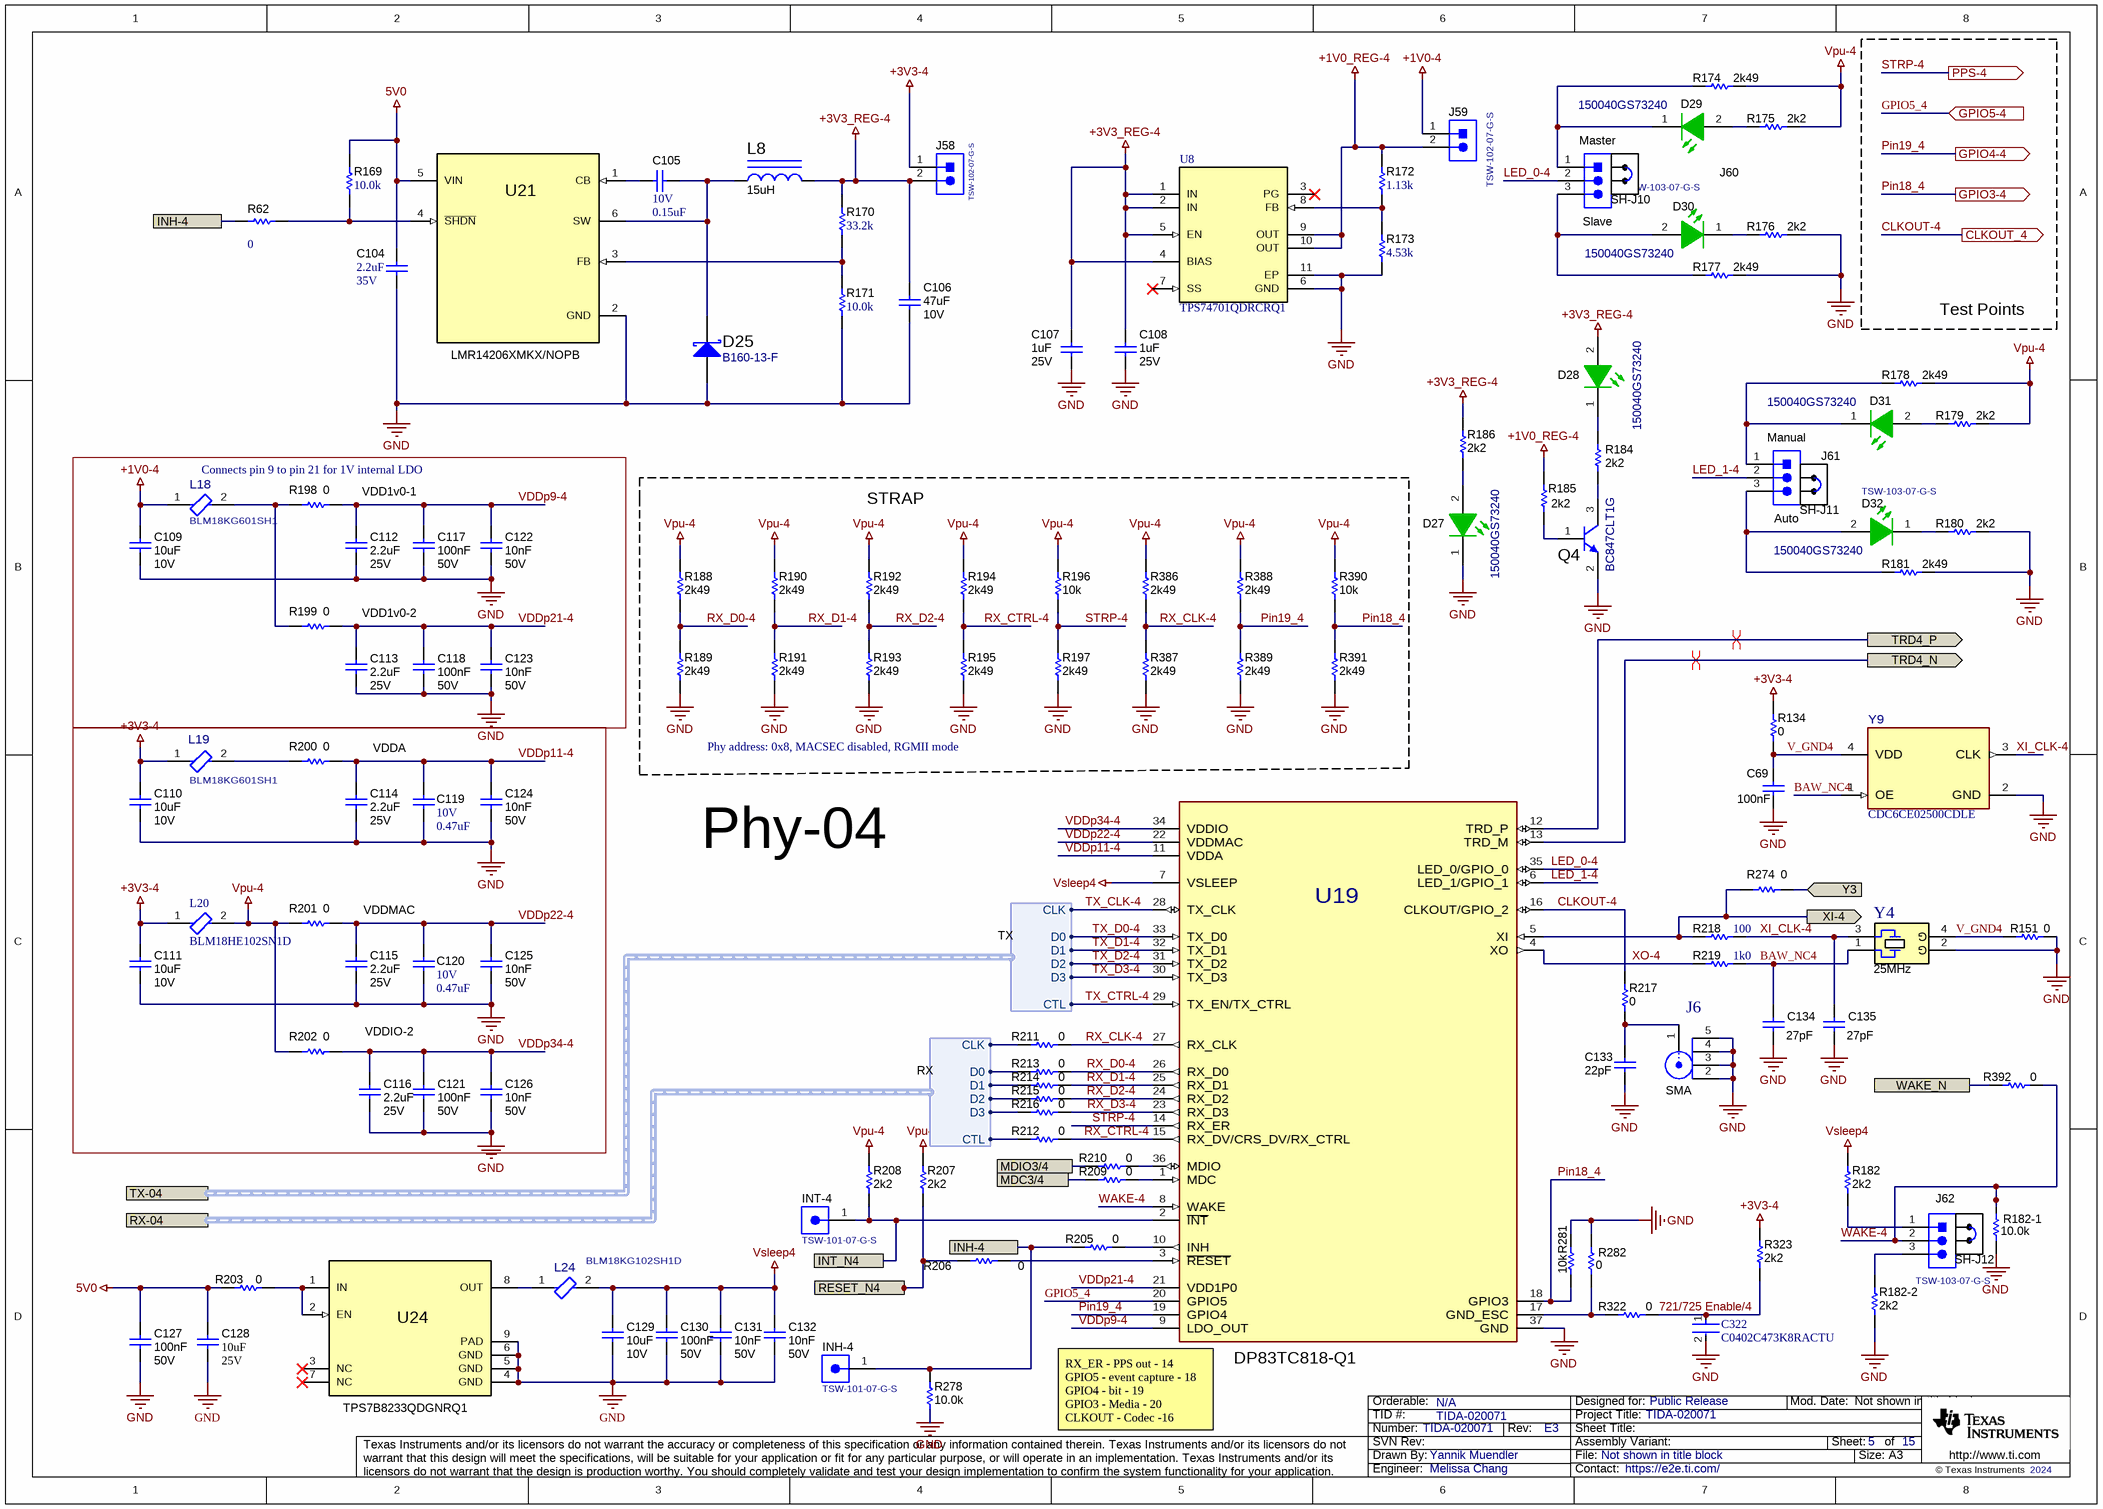
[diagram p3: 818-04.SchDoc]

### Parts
C69  ValueDisplayed: 100nF  [0402]  (hidden comment: C1005X5R1H104K050BB)
C104  VDC_V: 35V  ValueDisplayed: 2.2uF  [0603]  (hidden comment: C1608X5R1V225K080AC)
C105  VDC_V: 10V  ValueDisplayed: 0.15uF  [0402]  (hidden comment: GRM155R61A154KE19D)
C106  VDC_V: 10V  ValueDisplayed: 47uF  [0805_HV]  (hidden comment: C2012X5R1A476M125AC)
C107  VDC_V: 25V  ValueDisplayed: 1uF  [0402]  (hidden comment: GRM155R61E105KA12D)
C108  VDC_V: 25V  ValueDisplayed: 1uF  [0402]  (hidden comment: GRM155R61E105KA12D)
C109  VDC_V: 10V  ValueDisplayed: 10uF  [0402]  (hidden comment: GRM155R61A106ME11)
C110  VDC_V: 10V  ValueDisplayed: 10uF  [0402]  (hidden comment: GRM155R61A106ME11)
C111  VDC_V: 10V  ValueDisplayed: 10uF  [0402]  (hidden comment: GRM155R61A106ME11)
C112  VDC_V: 25V  ValueDisplayed: 2.2uF  [0402]  (hidden comment: C1005X5R1E225K050BC)
C113  VDC_V: 25V  ValueDisplayed: 2.2uF  [0402]  (hidden comment: C1005X5R1E225K050BC)
C114  VDC_V: 25V  ValueDisplayed: 2.2uF  [0402]  (hidden comment: C1005X5R1E225K050BC)
C115  VDC_V: 25V  ValueDisplayed: 2.2uF  [0402]  (hidden comment: C1005X5R1E225K050BC)
C116  VDC_V: 25V  ValueDisplayed: 2.2uF  [0402]  (hidden comment: C1005X5R1E225K050BC)
C117  VDC_V: 50V  ValueDisplayed: 100nF  [0402]  (hidden comment: C1005X5R1H104K050BB)
C118  VDC_V: 50V  ValueDisplayed: 100nF  [0402]  (hidden comment: C1005X5R1H104K050BB)
C119  VDC_V: 10V  ValueDisplayed: 0.47uF  [0402]  (hidden comment: GRM155R61A474KE15D)
C120  VDC_V: 10V  ValueDisplayed: 0.47uF  [0402]  (hidden comment: GRM155R61A474KE15D)
C121  VDC_V: 50V  ValueDisplayed: 100nF  [0402]  (hidden comment: C1005X5R1H104K050BB)
C122  VDC_V: 50V  ValueDisplayed: 10nF  [0402]  (hidden comment: C0402C103J5RACTU)
C123  VDC_V: 50V  ValueDisplayed: 10nF  [0402]  (hidden comment: C0402C103J5RACTU)
C124  VDC_V: 50V  ValueDisplayed: 10nF  [0402]  (hidden comment: C0402C103J5RACTU)
C125  VDC_V: 50V  ValueDisplayed: 10nF  [0402]  (hidden comment: C0402C103J5RACTU)
C126  VDC_V: 50V  ValueDisplayed: 10nF  [0402]  (hidden comment: C0402C103J5RACTU)
C127  VDC_V: 50V  ValueDisplayed: 100nF  [0402]  (hidden comment: C1005X5R1H104K050BB)
C128  VDC_V: 25V  ValueDisplayed: 10uF  [0603]  (hidden comment: C1608X5R1E106M080AC)
C129  VDC_V: 10V  ValueDisplayed: 10uF  [0402]  (hidden comment: GRM155R61A106ME11)
C130  VDC_V: 50V  ValueDisplayed: 100nF  [0402]  (hidden comment: C1005X5R1H104K050BB)
C131  VDC_V: 50V  ValueDisplayed: 10nF  [0402]  (hidden comment: C0402C103J5RACTU)
C132  VDC_V: 50V  ValueDisplayed: 10nF  [0402]  (hidden comment: C0402C103J5RACTU)
C133  ValueDisplayed: 22pF  [0402]  (hidden comment: GRM1555C1H220FA01D)
C134  ValueDisplayed: 27pF  [0402]  (hidden comment: C0402C270J5GACTU)
C135  ValueDisplayed: 27pF  [0402]  (hidden comment: C0402C270J5GACTU)
C322  C0402C473K8RACTU  [FP-C0402-BB-MFG]
D25  B160-13-F  [SMA]
D27  150040GS73240  [WL-SMCC_0402_Green]
D28  150040GS73240  [WL-SMCC_0402_Green]
D29  150040GS73240  [WL-SMCC_0402_Green]
D30  150040GS73240  [WL-SMCC_0402_Green]
D31  150040GS73240  [WL-SMCC_0402_Green]
D32  150040GS73240  [WL-SMCC_0402_Green]
INH-4  TSW-101-07-G-S  [TSW-101-07-G-S]
INT-4  TSW-101-07-G-S  [TSW-101-07-G-S]
J6  CompType: SMA  [AMPHENOL_901-144-8RFX]  (hidden comment: 901-144-8RFX)
J58  TSW-102-07-G-S  [TSW-102-07-G-S]
J59  TSW-102-07-G-S  [TSW-102-07-G-S]
J60  TSW-103-07-G-S  [TSW-103-07-G-S]
J61  TSW-103-07-G-S  [TSW-103-07-G-S]
J62  TSW-103-07-G-S  [TSW-103-07-G-S]
L8  ValueDisplayed: 15uH  [WE-TPC-LH]  (hidden comment: 744053150)
L18  BLM18KG601SH1  [FP-BLM18KG601SH1_0603 (1608 Metric)-MFG]
L19  BLM18KG601SH1  [FP-BLM18KG601SH1_0603 (1608 Metric)-MFG]
L20  BLM18HE102SN1D  [FP-BLM18-0_15-t0_8-MFG]
L24  BLM18KG102SH1D  [FP-BLM18KG102SH1D_0603-MFG]
Q4  BC847CLT1G  [SOT-23]
R62  ValueDisplayed: 0  [0402]  (hidden comment: CRCW04020000Z0ED)
R134  ValueDisplayed: 0  [0402]  (hidden comment: ERJ-2GE0R00X)
R151  ValueDisplayed: 0  [0402]  (hidden comment: ERJ-2GE0R00X)
R169  ValueDisplayed: 10.0k  [0402]  (hidden comment: CRCW040210K0FKED)
R170  ValueDisplayed: 33.2k  [0402]  (hidden comment: CRCW040233K2FKED)
R171  ValueDisplayed: 10.0k  [0402]  (hidden comment: CRCW040210K0FKED)
R172  ValueDisplayed: 1.13k  [0402]  (hidden comment: CRCW04021K13FKED)
R173  ValueDisplayed: 4.53k  [0402]  (hidden comment: CRCW04024K53FKED)
R174  ValueDisplayed: 2k49  [0402]  (hidden comment: CRCW04022K49FKED)
R175  ValueDisplayed: 2k2  [0402]  (hidden comment: CRCW04022K20JNED)
R176  ValueDisplayed: 2k2  [0402]  (hidden comment: CRCW04022K20JNED)
R177  ValueDisplayed: 2k49  [0402]  (hidden comment: CRCW04022K49FKED)
R178  ValueDisplayed: 2k49  [0402]  (hidden comment: CRCW04022K49FKED)
R179  ValueDisplayed: 2k2  [0402]  (hidden comment: CRCW04022K20JNED)
R180  ValueDisplayed: 2k2  [0402]  (hidden comment: CRCW04022K20JNED)
R181  ValueDisplayed: 2k49  [0402]  (hidden comment: CRCW04022K49FKED)
R182  ValueDisplayed: 2k2  [0402]  (hidden comment: CRCW04022K20JNED)
R182-1  ValueDisplayed: 10.0k  [0402]  (hidden comment: CRCW040210K0FKED)
R182-2  ValueDisplayed: 2k2  [0402]  (hidden comment: CRCW04022K20JNED)
R184  ValueDisplayed: 2k2  [0402]  (hidden comment: CRCW04022K20JNED)
R185  ValueDisplayed: 2k2  [0402]  (hidden comment: CRCW04022K20JNED)
R186  ValueDisplayed: 2k2  [0402]  (hidden comment: CRCW04022K20JNED)
R188  ValueDisplayed: 2k49  [0402]  (hidden comment: CRCW04022K49FKED)
R189  ValueDisplayed: 2k49  [0402]  (hidden comment: CRCW04022K49FKED)
R190  ValueDisplayed: 2k49  [0402]  (hidden comment: CRCW04022K49FKED)
R191  ValueDisplayed: 2k49  [0402]  (hidden comment: CRCW04022K49FKED)
R192  ValueDisplayed: 2k49  [0402]  (hidden comment: CRCW04022K49FKED)
R193  ValueDisplayed: 2k49  [0402]  (hidden comment: CRCW04022K49FKED)
R194  ValueDisplayed: 2k49  [0402]  (hidden comment: CRCW04022K49FKED)
R195  ValueDisplayed: 2k49  [0402]  (hidden comment: CRCW04022K49FKED)
R196  ValueDisplayed: 10k  [0402]  (hidden comment: RC0402FR-0710KL)
R197  ValueDisplayed: 2k49  [0402]  (hidden comment: CRCW04022K49FKED)
R198  ValueDisplayed: 0  [0402]  (hidden comment: CRCW04020000Z0EDHP)
R199  ValueDisplayed: 0  [0402]  (hidden comment: CRCW04020000Z0EDHP)
R200  ValueDisplayed: 0  [0402]  (hidden comment: CRCW04020000Z0EDHP)
R201  ValueDisplayed: 0  [0402]  (hidden comment: CRCW04020000Z0EDHP)
R202  ValueDisplayed: 0  [0402]  (hidden comment: CRCW04020000Z0EDHP)
R203  ValueDisplayed: 0  [0402]  (hidden comment: CRCW04020000Z0EDHP)
R205  ValueDisplayed: 0  [0402]  (hidden comment: CRCW04020000Z0EDHP)
R206  ValueDisplayed: 0  [0402]  (hidden comment: CRCW04020000Z0EDHP)
R207  ValueDisplayed: 2k2  [0402]  (hidden comment: CRCW04022K20JNED)
R208  ValueDisplayed: 2k2  [0402]  (hidden comment: CRCW04022K20JNED)
R209  ValueDisplayed: 0  [0402]  (hidden comment: CRCW04020000Z0EDHP)
R210  ValueDisplayed: 0  [0402]  (hidden comment: CRCW04020000Z0EDHP)
R211  ValueDisplayed: 0  [0402]  (hidden comment: CRCW04020000Z0EDHP)
R212  ValueDisplayed: 0  [0402]  (hidden comment: CRCW04020000Z0EDHP)
R213  ValueDisplayed: 0  [0402]  (hidden comment: CRCW04020000Z0EDHP)
R214  ValueDisplayed: 0  [0402]  (hidden comment: CRCW04020000Z0EDHP)
R215  ValueDisplayed: 0  [0402]  (hidden comment: CRCW04020000Z0EDHP)
R216  ValueDisplayed: 0  [0402]  (hidden comment: CRCW04020000Z0EDHP)
R217  ValueDisplayed: 0  [0402]  (hidden comment: ERJ-2GE0R00X)
R218  ValueDisplayed: 100  [0402]  (hidden comment: CRCW0402100RFKED)
R219  ValueDisplayed: 1k0  [0402]  (hidden comment: CRCW04021K00FKED)
R274  ValueDisplayed: 0  [0402]  (hidden comment: ERJ-2GE0R00X)
R278  ValueDisplayed: 10.0k  [0402]  (hidden comment: CRCW040210K0FKED)
R281  ValueDisplayed: 10k  [0402]  (hidden comment: ERJ-2RKF1002X)
R282  ValueDisplayed: 0  [0402]  (hidden comment: ERJ-2GE0R00X)
R322  ValueDisplayed: 0  [0402]  (hidden comment: CRCW04020000Z0EDHP)
R323  ValueDisplayed: 2k2  [0402]  (hidden comment: CRCW04022K20JNED)
R386  ValueDisplayed: 2k49  [0402]  (hidden comment: CRCW04022K49FKED)
R387  ValueDisplayed: 2k49  [0402]  (hidden comment: CRCW04022K49FKED)
R388  ValueDisplayed: 2k49  [0402]  (hidden comment: CRCW04022K49FKED)
R389  ValueDisplayed: 2k49  [0402]  (hidden comment: CRCW04022K49FKED)
R390  ValueDisplayed: 10k  [0402]  (hidden comment: RC0402FR-0710KL)
R391  ValueDisplayed: 2k49  [0402]  (hidden comment: CRCW04022K49FKED)
R392  ValueDisplayed: 0  [0402]  (hidden comment: CRCW04020000Z0EDHP)
SH-J10  881545-2  [TE_881545-2]  (value not drawn)  (mechanical)
SH-J11  881545-2  [TE_881545-2]  (value not drawn)  (mechanical)
SH-J12  881545-2  [TE_881545-2]  (value not drawn)  (mechanical)
U8  TPS74701QDRCRQ1  [DRC0010A]
U19  PartNumber: DP83TC818-Q1  [RHA0036A-MFG]  (hidden comment: DP83TC812R-Q1)
U21  LMR14206XMKX/NOPB  [DDC0006A_N]
U24  TPS7B8233QDGNRQ1  [DGN0008D_N]
Y4  Frequency_Fixed: 25MHz  [Abracon_ABM8AIG]  (hidden comment: ABM8AIG-25.000MHZ-12-2Z-T3)
Y9  CDC6CE02500CDLE  [DLE0004A-MFG]

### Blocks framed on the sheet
STRAP: R188-R197 R386-R391

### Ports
CLKOUT_4 (out), GPIO3-4 (out), GPIO4-4 (out), GPIO5-4 (in), INH-4, INT_N4, MDC3/4, MDIO3/4, PPS-4 (out), RESET_N4, RX-04 (harness RX), TRD4_N (out), TRD4_P (out), TX-04 (harness TX), WAKE_N, XI-4 (out), Y3 (in)

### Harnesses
TX: D0, D1, D2, D3, CTL, CLK
RX: D0, D1, D2, D3, CTL, CLK

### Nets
5V0: C104.1 C127.1 C128.1 R169.2 R203.2 U21.5(VIN)
+1V0-4: C109.1 J59.1 L18.1
+1V0_REG-4: J59.2 R172.2 R185.2 U8.9(OUT) U8.10(OUT)
+3V3-4: C110.1 C111.1 J58.1 L19.1 L20.1 R134.1 R323.1
+3V3_REG-4: C106.1 C107.1 C108.1 D28.2(A) J58.2 L8.2 R170.2 R186.2 U8.1(IN) U8.2(IN) U8.4(BIAS) U8.5(EN)
GND: C69.2 C104.2 C106.2 C107.2 C108.2 C109.2 C110.2 C111.2 C112.2 C113.2 C114.2 C115.2 C116.2 C117.2 C118.2 C119.2 C120.2 C121.2 C122.2 C123.2 C124.2 C125.2 C126.2 C127.2 C128.2 C129.2 C130.2 C131.2 C132.2 C133.2 C134.2 C135.2 C322.2 D25.2(A) D27.1(K) J6.2 J6.3 J6.4 J6.5 Q4.2(E) R151.2 R171.1 R173.1 R176.2 R177.2 R180.2 R181.2 R182-1.1 R182-2.2 R189.1 R191.1 R193.1 R195.1 R197.1 R278.1 R281.1 R282.1 R387.1 R389.1 R391.1 U8.6(GND) U8.11(EP) U19.37(GND) U21.2(GND) U24.4(GND) U24.5(GND) U24.6(GND) U24.9(PAD) Y4.2(GND) Y9.2(GND)
Vpu-4: L20.2 R174.2 R175.2 R178.2 R179.2 R188.2 R190.2 R192.2 R194.2 R196.2 R201.2 R202.2 R207.2 R208.2 R386.2 R388.2 R390.2
Vsleep4: C129.1 C130.1 C131.1 C132.1 L24.2 R182.1 U19.7(VSLEEP)
721/725 Enable/4: C322.1 R322.1 R323.2
BAW_NC4: C134.1 R219.1 Y4.1 Y9.1(OE)
CLKOUT-4: R217.1 U19.16(CLKOUT/GPIO_2) ; port CLKOUT_4
GPIO5_4: U19.20(GPIO5) ; port GPIO5-4
INH-4: INH-4.1 R62.1 R205.2 R278.2 ; port INH-4
INT_N4: INT-4.1 R208.1 U19.2(~{INT}) ; port INT_N4
LED_0-4: J60.2 U19.35(LED_0/GPIO_0)
LED_1-4: J61.2 U19.6(LED_1/GPIO_1)
MDC3/4: R209.2 ; port MDC3/4
MDIO3/4: R210.2 ; port MDIO3/4
P0-R2-RCLK: R211.2 ; port RX-04.CLK
P0-R2-RCTL: R212.2 ; port RX-04.CTL
P0-R2-RD0: R213.2 ; port RX-04.D0
P0-R2-RD1: R214.2 ; port RX-04.D1
P0-R2-RD2: R215.2 ; port RX-04.D2
P0-R2-RD3: R216.2 ; port RX-04.D3
Pin18_4: R281.2 R390.1 R391.2 U19.18(GPIO3) ; port GPIO3-4
Pin19_4: R388.1 R389.2 U19.19(GPIO4) ; port GPIO4-4
RESET_N4: R206.2 R207.1 ; port RESET_N4
RX_CLK-4: R211.1 R386.1 R387.2 U19.27(RX_CLK)
RX_CTRL-4: R194.1 R195.2 R212.1 U19.15(RX_DV/CRS_DV/RX_CTRL)
RX_D0-4: R188.1 R189.2 R213.1 U19.26(RX_D0)
RX_D1-4: R190.1 R191.2 R214.1 U19.25(RX_D1)
RX_D2-4: R192.1 R193.2 R215.1 U19.24(RX_D2)
RX_D3-4: R216.1 U19.23(RX_D3)
STRP-4: R196.1 R197.2 U19.14(RX_ER) ; port PPS-4
TRD4_N: U19.13(TRD_M) ; port TRD4_N
TRD4_P: U19.12(TRD_P) ; port TRD4_P
TX_CLK-4: U19.28(TX_CLK) ; port TX-04.CLK
TX_CTRL-4: U19.29(TX_EN/TX_CTRL) ; port TX-04.CTL
TX_D0-4: U19.33(TX_D0) ; port TX-04.D0
TX_D1-4: U19.32(TX_D1) ; port TX-04.D1
TX_D2-4: U19.31(TX_D2) ; port TX-04.D2
TX_D3-4: U19.30(TX_D3) ; port TX-04.D3
V_GND4: C69.1 R134.2 R151.1 Y4.4(GND) Y9.4(VDD)
VDDp9-4: C112.1 C117.1 C122.1 R198.1 U19.9(LDO_OUT)
VDDp11-4: C114.1 C119.1 C124.1 R200.1 U19.11(VDDA)
VDDp21-4: C113.1 C118.1 C123.1 R199.1 U19.21(VDD1P0)
VDDp22-4: C115.1 C120.1 C125.1 R201.1 U19.22(VDDMAC)
VDDp34-4: C116.1 C121.1 C126.1 R202.1 U19.34(VDDIO)
WAKE-4: J62.2 R182-1.2 R392.1 U19.8(WAKE)
WAKE_N: R392.2 ; port WAKE_N
XI-4: R218.2 R274.1 U19.5(XI) ; port XI-4
XI_CLK-4: C135.1 R218.1 Y4.3 Y9.3(CLK)
XO-4: R219.2 U19.4(XO)
Y3: R274.2 ; port Y3
NetC105_1: C105.1 D25.1(K) L8.1 U21.6(SW)
NetC105_2: C105.2 U21.1(CB)
NetC133_1: C133.1 J6.1 R217.2
NetD27_2: D27.2(A) R186.1
NetD28_1: D28.1(K) R184.2
NetD29_1: D29.1(K) J60.1 R174.1
NetD29_2: D29.2(A) R175.1
NetD30_1: D30.1(K) R176.1
NetD30_2: D30.2(A) J60.3 R177.1
NetD31_1: D31.1(K) J61.1 R178.1
NetD31_2: D31.2(A) R179.1
NetD32_1: D32.1(K) R180.1
NetD32_2: D32.2(A) J61.3 R181.1
NetJ62_1: J62.1 R182.2
NetJ62_3: J62.3 R182-2.1
NetL18_2: L18.2 R198.2 R199.2
NetL19_2: L19.2 R200.2
NetL24_1: L24.1 U24.8(OUT)
NetQ4_1: Q4.1(B) R185.1
NetQ4_3: Q4.3(C) R184.1
NetR62_2: R62.2 R169.1 U21.4(~{SHDN})
NetR170_1: R170.1 R171.2 U21.3(FB)
NetR172_1: R172.1 R173.2 U8.8(FB)
NetR203_1: R203.1 U24.1(IN) U24.2(EN)
NetR205_1: R205.1 U19.10(INH)
NetR206_1: R206.1 U19.3(~{RESET})
NetR209_1: R209.1 U19.1(MDC)
NetR210_1: R210.1 U19.36(MDIO)
NetR282_2: R282.2 R322.2 U19.17(GND_ESC)

Not connected (* = marked no-connect by the designer): U8 3(PG)* 7(SS)*; U24 3(NC)* 7(NC)*

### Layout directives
differential pair: TRD4_N, TRD4_P

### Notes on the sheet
- (near J60) Master
- (near J60) Slave
- Test Points
- (near J61) Manual
- Connects pin 9 to pin 21 for 1V internal LDO
- VDD1v0-1
- Auto
- VDD1v0-2
- VDDA
- Phy address: 0x8, MACSEC disabled, RGMII mode
- Phy-04
- VDDMAC
- VDDIO-2
- (near U19) RX_ER - PPS out - 14
  GPIO5 - event capture - 18
  GPIO4 - bit - 19                                     GPIO3 - Media - 20
  CLKOUT - Codec -16

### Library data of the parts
C69 = CMP-0006279-2: as C68 on sheet 818-03
C104 = CMP-0007020-5: as C70 on sheet 818-03
C105 = CMP-0006567-2: as C71 on sheet 818-03
C106 = CMP-0007825-2: as C72 on sheet 818-03
C107 C108 = CMP-0006608-2: as C73 on sheet 818-03
C109-C111 C129 = CMP-0006564-2: as C75-C77 on sheet 818-03
C112-C116 = CMP-0006278-2: as C78-C82 on sheet 818-03
C117 C118 C121 C127 C130 = CMP-0006279-2: as C83 on sheet 818-03
C119 C120 = CMP-0006580-2: as C85 on sheet 818-03
C122-C126 C131 C132 = CMP-0006236-2: as C88-C92 on sheet 818-03
C128 = CMP-0007007-5: as C94 on sheet 818-03
C133 = CMP-0006438-2: as C99 on sheet 818-03
C134 C135 = CMP-0750098-1: as C100 on sheet 818-03
C322 = CMP-2008-02147-2: as C320 on sheet 818-03
D25 = CMP-0028389-2: as D17 on sheet 818-03
D27-D32 = CMP-0081765-2: as D19-D24 on sheet 818-03
INH-4 INT-4 = CMP-0075403-1: as INH-3 on sheet 818-03
J6 = CMP-0055833-1: as J5 on sheet 818-03
J58 J59 = CMP-0075405-3: as J43 on sheet 818-03
J60-J62 = CMP-0075407-2: as J45-J47 on sheet 818-03
L8 = CMP-0064420-2: as L7 on sheet 818-03
L18 L19 = CMP-0089848-1: as L16 on sheet 818-03
L20 = CMP-0686-00363-3: as L15 on sheet 818-03
L24 = CMP-0089381-1: as L23 on sheet 818-03
Q4 = CMP-0000376-2: as Q3 on sheet 818-03
R62 = CMP-0026822-1: as R45 on sheet 818-03
R134 R151 R217 R274 R282 = CMP-0026992-3: as R115 on sheet 818-03
R169 R171 = CMP-0025958-3: as R116 on sheet 818-03
R170 = CMP-0026298-2: as R117 on sheet 818-03
R172 = CMP-0026076-3: as R119 on sheet 818-03
R173 = CMP-0026410-2: as R120 on sheet 818-03
R174 R177 R178 R181 R188-R195 R197 R386-R389 R391 = CMP-0026237-2: as R121 on sheet 818-03
R175 R176 R179 R180 R182 R182-2 R184-R186 R207 R208 R323 = CMP-0026890-5: as R122 on sheet 818-03
R182-1 R278 = CMP-0025958-1: as R129-1 on sheet 818-03
R196 R390 = CMP-0078669-1: RES, 10.0 k, 1%, 0.063 W, 0402; Manufacturer: Yageo America; Power_W: 63mW; Green_Lifecycle: Active; TempCo: 100 ppm/C; Value_Code: 10k0; Green_REACh: Passed; Value: 10.0k; EIA_Code: E96; SizeX_mm: 1; SizeY_mm: 0.5; SizeZ_mm: 0.6; Value2: 0.063W; AEC Qualified: N; AEC Category: Q200
R198-R203 R205 R206 R209-R216 R322 R392 = CMP-0081856-1: as R145-R150 on sheet 818-03
R218 = CMP-0025951-3: as R165 on sheet 818-03
R219 = CMP-0026071-3: as R166 on sheet 818-03
R281 = CMP-0026992-3: as R279 on sheet 818-03
SH-J10-SH-J12 = 881545-2: as SH-J5 on sheet 818-03
U8 = CMP-0036364-1: as U5 on sheet 818-03
U19 = CMP-0089064-1: as U13 on sheet 818-03
U21 = CMP-0076377-2: as U15 on sheet 818-03
U24 = CMP-0013312-4: as U18 on sheet 818-03
Y4 = CMP-0004682-5: as Y3 on sheet 818-03
Y9 = CMP-0001498-1: as Y8 on sheet 818-03

## Sheet CLOCK.SchDoc
size A4; Date: Not shown in title block; ApprovedBy: Not shown in title block; CheckedBy: Not shown in title block; Author: Not shown in title block; CompanyName: Not shown in title block; Engineer: Not shown in title block; Organization: Not shown in title block; Address1: Not shown in title block; Address2: Not shown in title block; Address3: Not shown in title block; Address4: Not shown in title block; DocumentNumber: 10; Revision: Use project parameter SCH_Rev; SheetNumber: 10; SheetTotal: 15; PageSetup: Record=PageOptions¦CenterHorizontal=True¦CenterVertical=True¦PrintScale=1.00¦XCorrection=1.00¦YCorrection=1.00¦PrintKind=0¦BorderSize=5000000¦LeftOffset=0¦BottomOffset=0¦Orientation=2¦PaperLength=1000¦PaperWidth=1000¦Scale=100¦PaperSource=15¦PrintQuality=600¦MediaType=1¦DitherType=10¦PaperKind=Letter¦PrintScaleMode=1
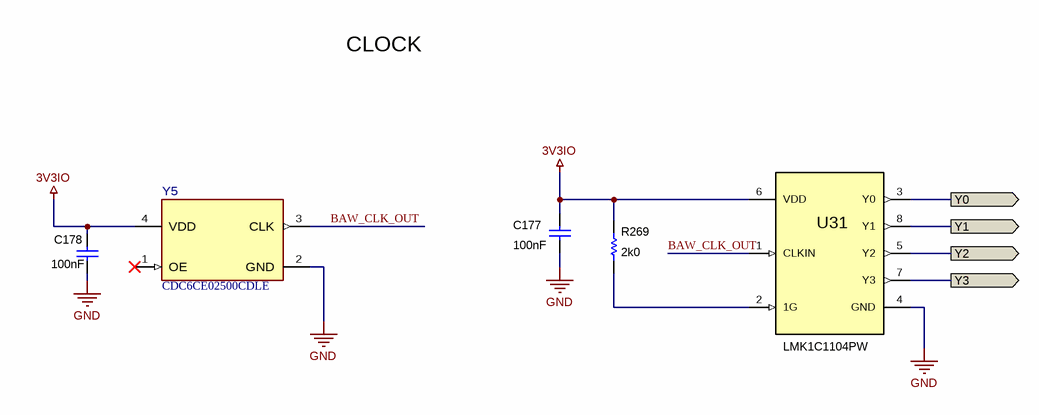
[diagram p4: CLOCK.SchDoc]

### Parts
C177  ValueDisplayed: 100nF  [0402]  (hidden comment: C1005X5R1H104K050BB)
C178  ValueDisplayed: 100nF  [0402]  (hidden comment: C1005X5R1H104K050BB)
R269  ValueDisplayed: 2k0  [0402]  (hidden comment: RG1005P-202-B-T5)
U31  LMK1C1104PW  [PW0008A_N]
Y5  CDC6CE02500CDLE  [DLE0004A-MFG]

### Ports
Y0 (out), Y1 (out), Y2 (out), Y3 (out)

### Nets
3V3IO: C177.1 C178.1 R269.2 U31.6(VDD) Y5.4(VDD)
GND: C177.2 C178.2 U31.4(GND) Y5.2(GND)
BAW_CLK_OUT: U31.1(CLKIN) Y5.3(CLK)
Y0: U31.3(Y0) ; port Y0
Y1: U31.8(Y1) ; port Y1
Y2: U31.5(Y2) ; port Y2
Y3: U31.7(Y3) ; port Y3
NetR269_1: R269.1 U31.2(1G)

Not connected (* = marked no-connect by the designer): Y5 1(OE)*

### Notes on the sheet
- CLOCK

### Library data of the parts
C177 C178 = CMP-0006279-2: as C68 on sheet 818-03
R269 = CMP-0026816-1: RES, 2.00 k, 0.1%, 0.063 W, 0402; Manufacturer: Susumu Co Ltd; Power_W: 63mW; TempCo: 25 ppm/C; Value_Code: 2k00; U/M: EA; Value: 2.00k; EIA_Code: E192; Res_ohm: 2k; SizeX_mm: 1; SizeY_mm: 0.5; SizeZ_mm: 0.6; Value2: 0.063W; AEC Category: Q200
U31 = CMP-0860874-2: 3.3-V and 2.5-V LVCMOS High-Performance Clock Buffer Family, PW0008A (TSSOP-8); Alternate PartNumber: LMK1C1104PWR; Manufacturer: Texas Instruments; AEC Qualified: N; SizeZ_mm: 1.2; SizeY_mm: 3; SizeArea_mm2: 19.2; CompType: IC; SizeX_mm: 6.4; SizeAreaWB_mm2: 42; AEC Category: Q200
Y5 = CMP-0001498-1: as Y8 on sheet 818-03

## Sheet AVB Headers.SchDoc
size 431 x 279 mm; Date: Not shown in title block; ApprovedBy: Not shown in title block; CheckedBy: Not shown in title block; Author: Not shown in title block; CompanyName: Not shown in title block; Engineer: Not shown in title block; Organization: Not shown in title block; Address1: Not shown in title block; Address2: Not shown in title block; Address3: Not shown in title block; Address4: Not shown in title block; DocumentNumber: 11; Revision: Use project parameter SCH_Rev; SheetNumber: 11; SheetTotal: 15; PageSetup: Record=PageOptions¦CenterHorizontal=True¦CenterVertical=True¦PrintScale=1.00¦XCorrection=1.00¦YCorrection=1.00¦PrintKind=0¦BorderSize=5000000¦LeftOffset=0¦BottomOffset=0¦Orientation=2¦PaperLength=1000¦PaperWidth=1000¦Scale=100¦PaperSource=15¦PrintQuality=600¦MediaType=1¦DitherType=10¦PaperKind=Letter¦PrintScaleMode=1
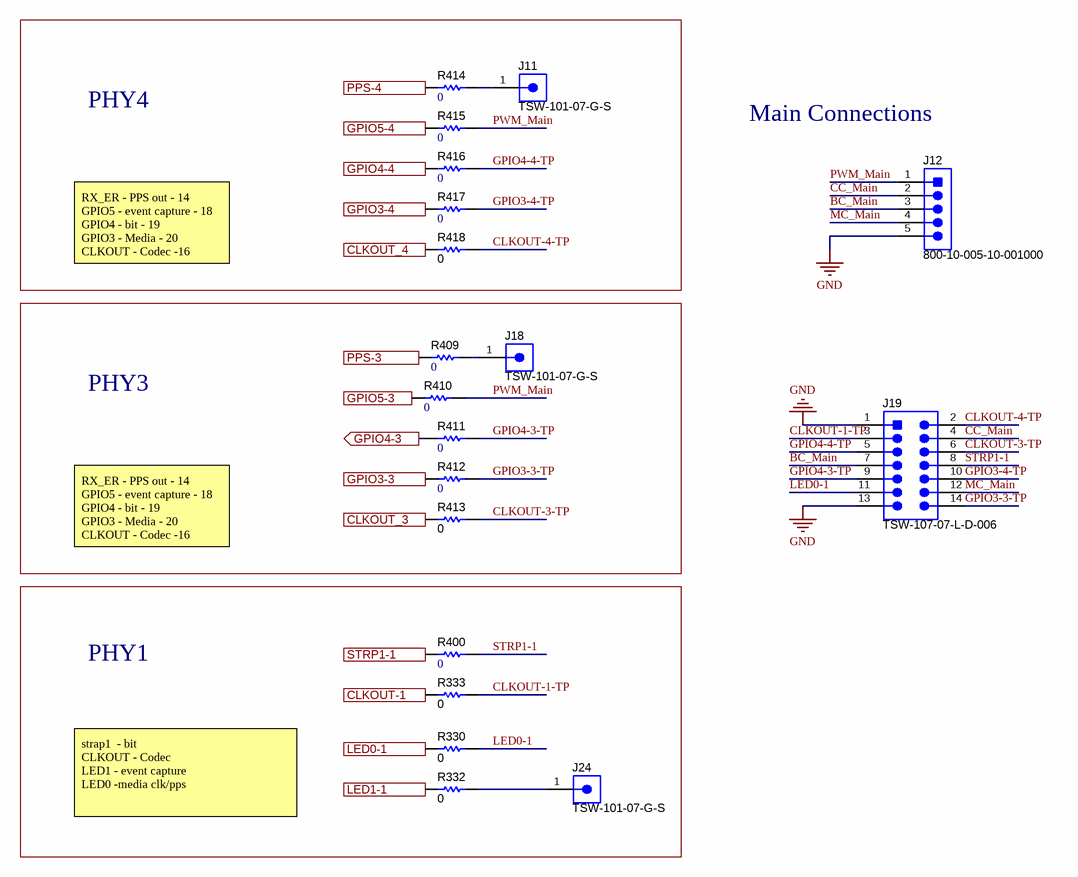
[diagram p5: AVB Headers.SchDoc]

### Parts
J11  TSW-101-07-G-S  [TSW-101-07-G-S]
J12  800-10-005-10-001000  [Mill-Max_800-10-005-10-001000]
J18  TSW-101-07-G-S  [TSW-101-07-G-S]
J19  TSW-107-07-L-D-006  [TSW-107-07-G-D]
J24  TSW-101-07-G-S  [TSW-101-07-G-S]
R330  ValueDisplayed: 0  [0402]  (hidden comment: ERJ-2GE0R00X)
R332  ValueDisplayed: 0  [0402]  (hidden comment: ERJ-2GE0R00X)
R333  ValueDisplayed: 0  [0402]  (hidden comment: ERJ-2GE0R00X)
R400  ValueDisplayed: 0  [0402]  (hidden comment: ERJ-2GE0R00X)
R409  ValueDisplayed: 0  [0402]  (hidden comment: ERJ-2GE0R00X)
R410  ValueDisplayed: 0  [0402]  (hidden comment: ERJ-2GE0R00X)
R411  ValueDisplayed: 0  [0402]  (hidden comment: ERJ-2GE0R00X)
R412  ValueDisplayed: 0  [0402]  (hidden comment: ERJ-2GE0R00X)
R413  ValueDisplayed: 0  [0402]  (hidden comment: ERJ-2GE0R00X)
R414  ValueDisplayed: 0  [0402]  (hidden comment: ERJ-2GE0R00X)
R415  ValueDisplayed: 0  [0402]  (hidden comment: ERJ-2GE0R00X)
R416  ValueDisplayed: 0  [0402]  (hidden comment: ERJ-2GE0R00X)
R417  ValueDisplayed: 0  [0402]  (hidden comment: ERJ-2GE0R00X)
R418  ValueDisplayed: 0  [0402]  (hidden comment: ERJ-2GE0R00X)

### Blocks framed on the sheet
PHY4: J11 R414-R418
PHY3: J18 R409-R413
PHY1: J24 R330 R332 R333 R400

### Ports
CLKOUT-1 (out), CLKOUT_3 (out), CLKOUT_4 (out), GPIO3-3 (out), GPIO3-4 (out), GPIO4-3 (out), GPIO4-4 (out), GPIO5-3 (in), GPIO5-4 (in), LED0-1 (out), LED1-1 (in), PPS-3 (out), PPS-4 (out), STRP1-1 (out)

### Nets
GND: J12.5 J19.1 J19.13
BC_Main: J12.3 J19.7
CC_Main: J12.2 J19.4
CLKOUT-1: R333.1 ; port CLKOUT-1
CLKOUT-1-TP: J19.3 R333.2
CLKOUT-3: R413.1 ; port CLKOUT_3
CLKOUT-3-TP: J19.6 R413.2
CLKOUT-4: R418.1 ; port CLKOUT_4
CLKOUT-4-TP: J19.2 R418.2
GPIO3-3-TP: J19.14 R412.2
GPIO3-4-TP: J19.10 R417.2
GPIO4-3-TP: J19.9 R411.2
GPIO4-4-TP: J19.5 R416.2
GPIO5_3: R410.1 ; port GPIO5-3
GPIO5_4: R415.1 ; port GPIO5-4
LED0-1: J19.11 R330.2
LED_0-1: R330.1 ; port LED0-1
LED_1-1: R332.1 ; port LED1-1
MC_Main: J12.4 J19.12
Pin18_3: R412.1 ; port GPIO3-3
Pin18_4: R417.1 ; port GPIO3-4
Pin19_3: R411.1 ; port GPIO4-3
Pin19_4: R416.1 ; port GPIO4-4
PWM_Main: J12.1 R410.2 R415.2
STRP1-1: J19.8 R400.2
STRP-1: R400.1 ; port STRP1-1
STRP-3: R409.1 ; port PPS-3
STRP-4: R414.1 ; port PPS-4
NetJ11_1: J11.1 R414.2
NetJ18_1: J18.1 R409.2
NetJ24_1: J24.1 R332.2

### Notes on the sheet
- Main Connections
- RX_ER - PPS out - 14
  GPIO5 - event capture - 18
  GPIO4 - bit - 19                                     GPIO3 - Media - 20
  CLKOUT - Codec -16
- strap1  - bit
  CLKOUT - Codec                                     LED1 - event capture                                          LED0 -media clk/pps

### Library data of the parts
J11 J18 J24 = CMP-0075403-1: as INH-3 on sheet 818-03
J12 = CMP-0055088-1: Header, 100mil, 5x1, TH; Manufacturer: Mill-Max; CT: FALSE; CNHeader: TRUE
J19 = CMP-0081507-1: Header, 2.54mm, 7x2, Gold with Tin tail, TH; Manufacturer: Samtec; Pitch_mm: 2.54; Gender: Male; Cert_UL: Y; Shrouded: N; Row_Count: 2
R330 R332 R333 R413 R418 = CMP-0026992-3: as R115 on sheet 818-03
R400 R409-R412 R414-R417 = CMP-0026992-3: RES, 0, 5%, 0.1 W, AEC-Q200 Grade 0, 0402; Manufacturer: Panasonic; Power_W: 100mW; TempCo: 600 ppm/C; Value_Code: 0000; Value: 0; EIA_Code: E24; SizeX_mm: 1; SizeY_mm: 0.5; SizeZ_mm: 0.6; Value2: 0.1W; AEC Qualified: Y; VDC_V: 50V; AEC Category: Q200; SizeAreaWB_mm2: 3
